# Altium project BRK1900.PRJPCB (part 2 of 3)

## Sheet Expansion-MC2.SchDoc: BRK1900 - Expansion MC2
size C; Organization: Opal Kelly; Address1: 13500 SW 72nd Ave STE 100; Address2: Portland, OR  97223; Address3: 217.391.3724; Address4: http://www.opalkelly.com; DocumentNumber: 3; Revision: 1; SheetNumber: 3; SheetTotal: 11; PageSetup: Record=PageOptions¦CenterHorizontal=True¦CenterVertical=True¦PrintScale=0.52¦XCorrection=1.00¦YCorrection=1.00¦PrintKind=0¦BorderSize=5000000¦LeftOffset=0¦BottomOffset=0¦Orientation=2¦PaperLength=1000¦PaperWidth=1000¦Scale=100¦PaperSource=7¦PrintQuality=-4¦MediaType=1¦DitherType=10¦PaperKind=Letter¦PrintScaleMode=1
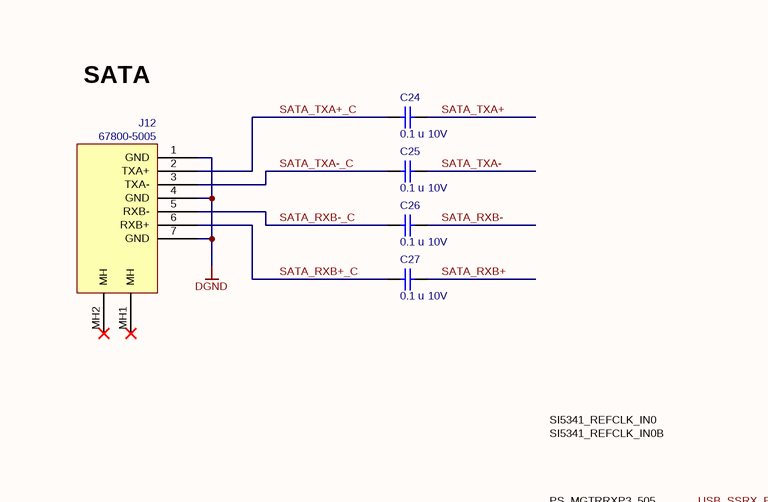
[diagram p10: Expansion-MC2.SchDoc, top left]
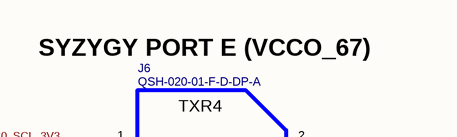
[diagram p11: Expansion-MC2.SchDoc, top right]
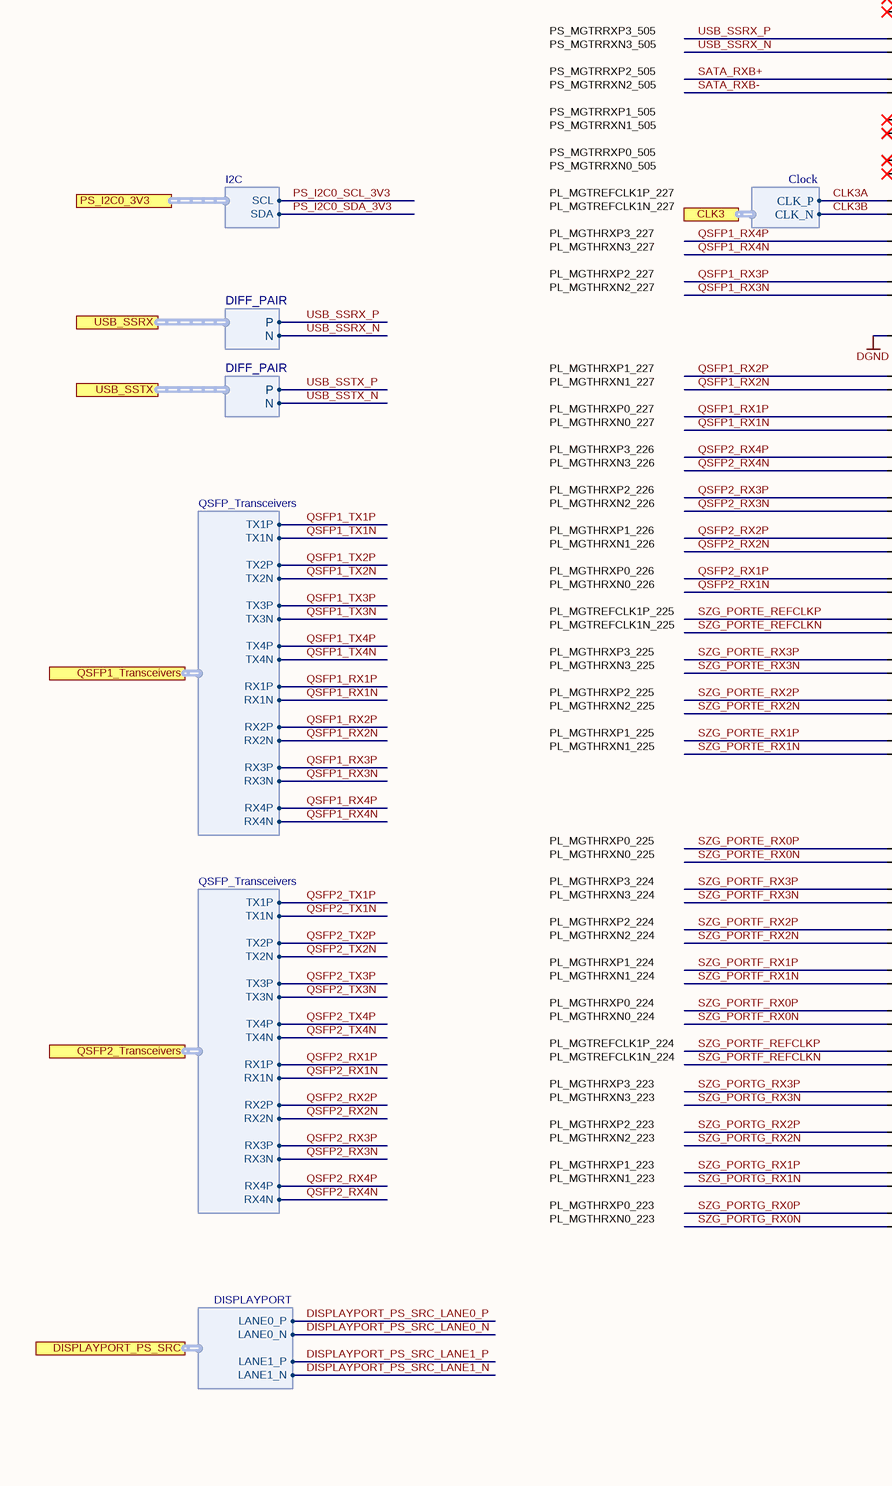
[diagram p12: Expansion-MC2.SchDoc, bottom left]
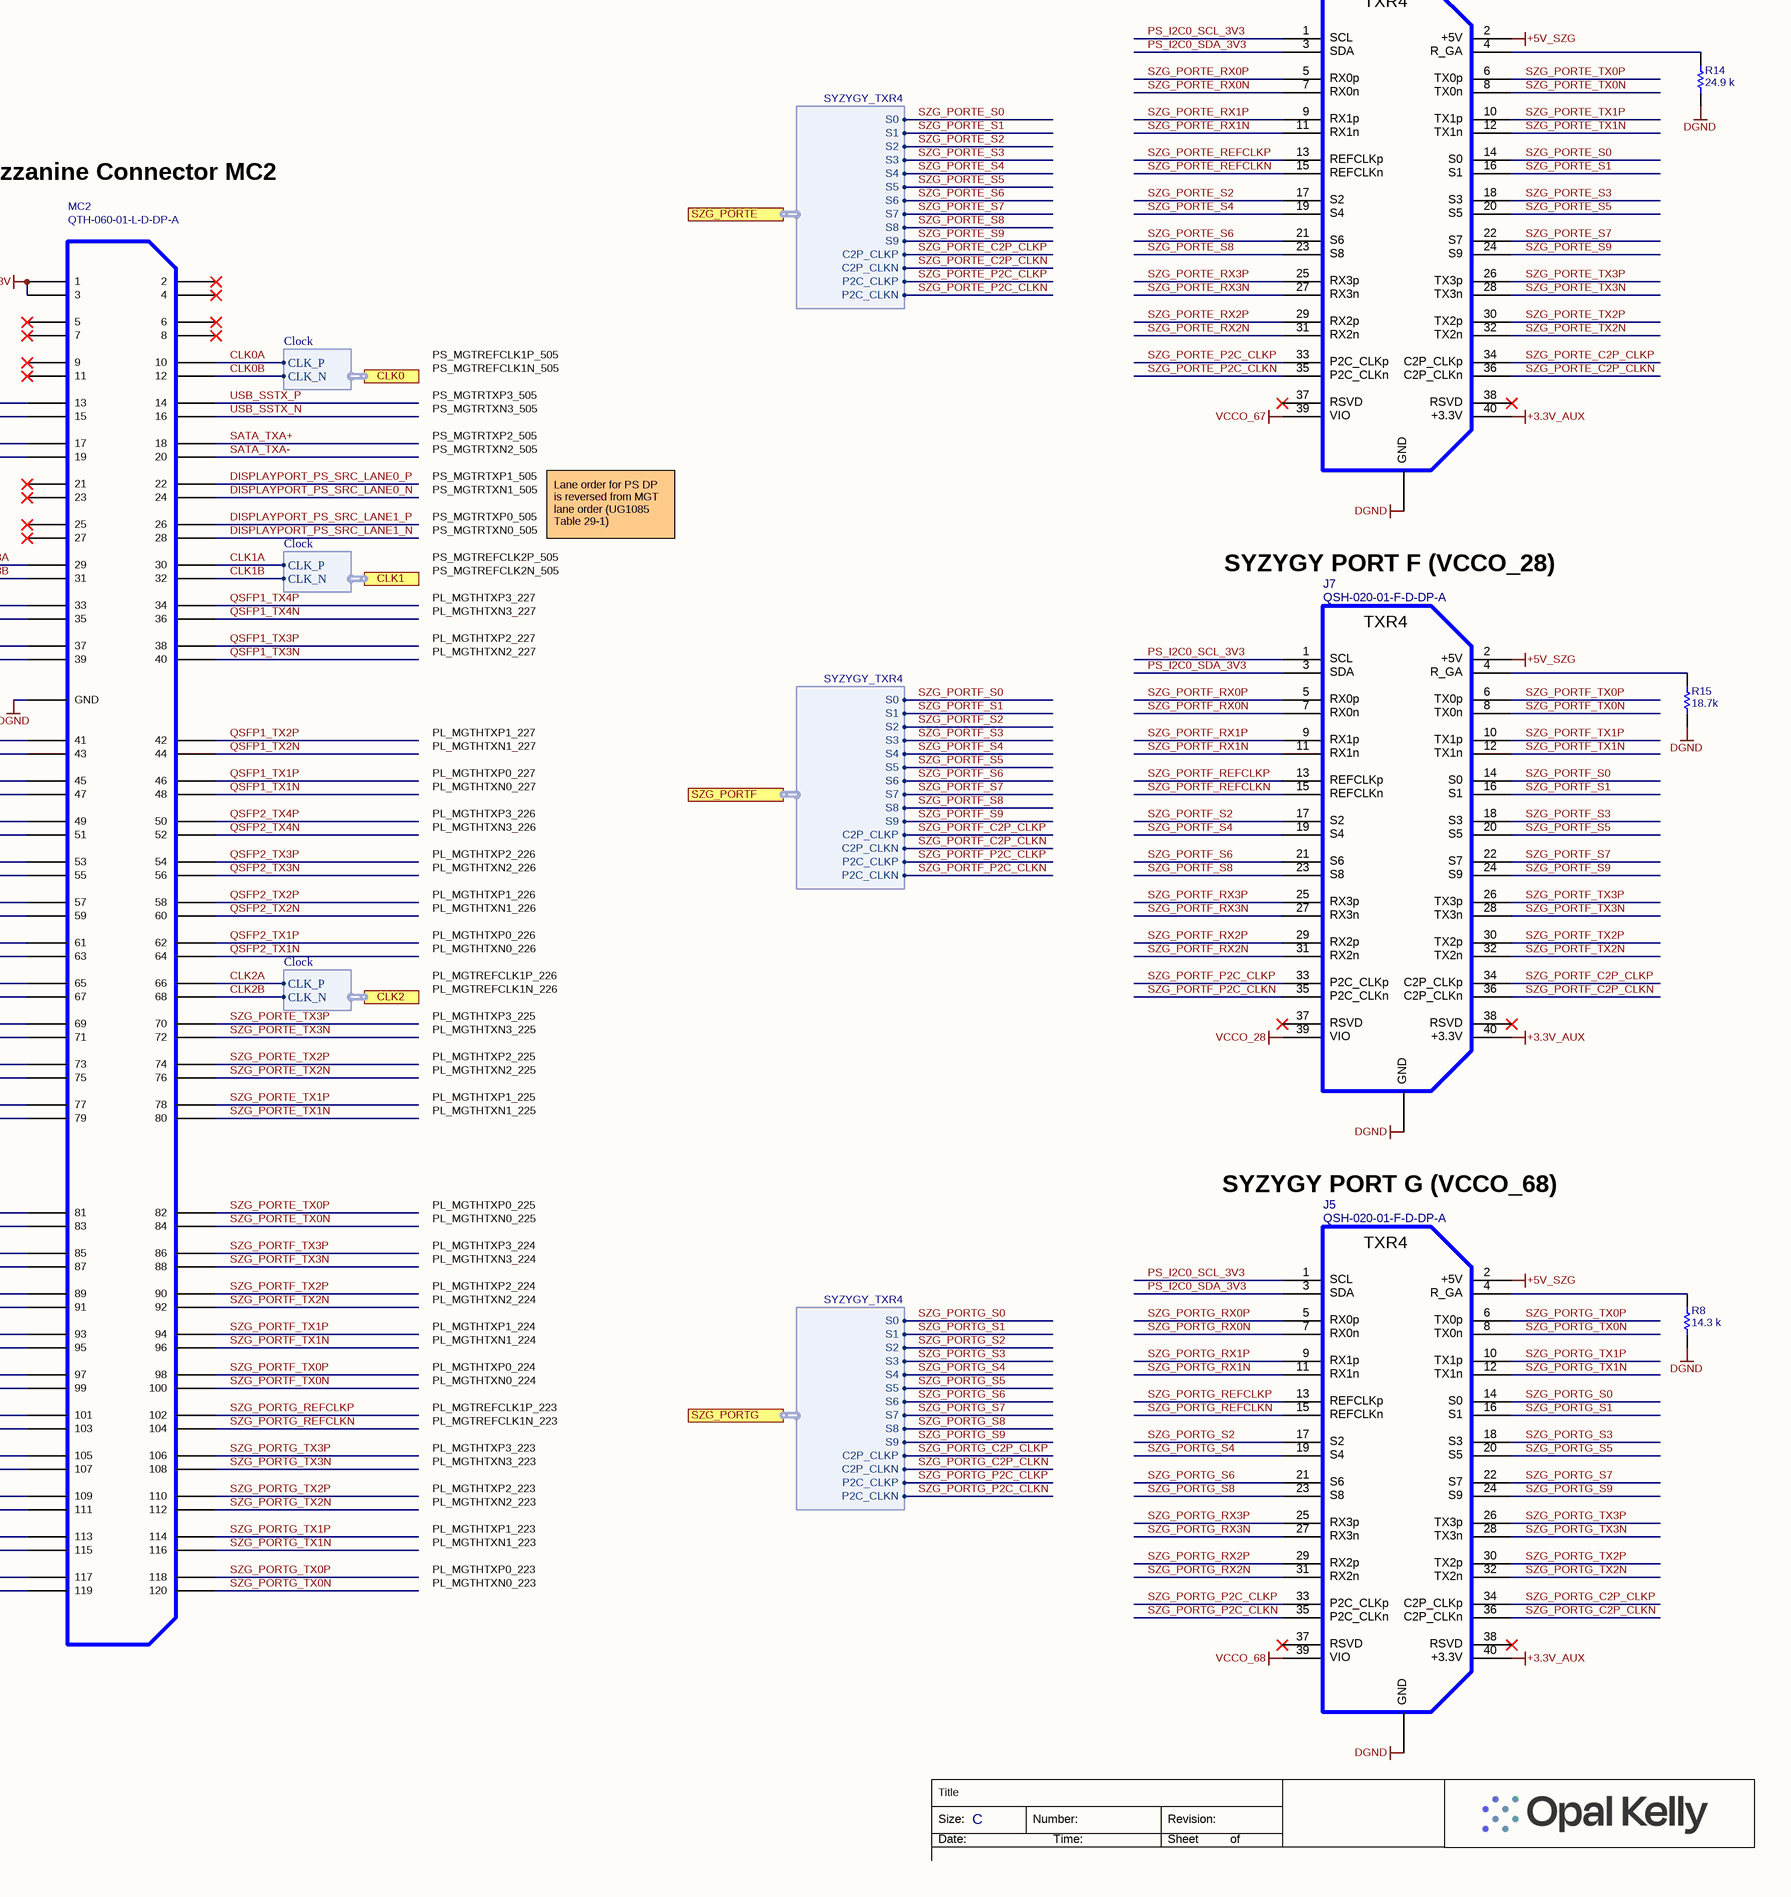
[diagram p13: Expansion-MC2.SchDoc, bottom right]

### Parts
C24  value 0.1 u  Voltage: 10V  [CAPC1005X06A]  (hidden comment: SM-0402, 10%, 10v)
C25  value 0.1 u  Voltage: 10V  [CAPC1005X06A]  (hidden comment: SM-0402, 10%, 10v)
C26  value 0.1 u  Voltage: 10V  [CAPC1005X06A]  (hidden comment: SM-0402, 10%, 10v)
C27  value 0.1 u  Voltage: 10V  [CAPC1005X06A]  (hidden comment: SM-0402, 10%, 10v)
J5  QSH-020-01-F-D-DP-A  [QSH-020-01-X-D-DP-A-L-SYZYGY]
J6  QSH-020-01-F-D-DP-A  [QSH-020-01-X-D-DP-A-L-SYZYGY]
J7  QSH-020-01-F-D-DP-A  [QSH-020-01-X-D-DP-A-L-SYZYGY]
J12  67800-5005  [MOLEX-67800-5005]
MC2  QTH-060-01-L-D-DP-A  [QTH-060-01-X-D-DP-A]
R8  value 14.3 k  [RESC1005X06A]  (hidden comment: RC0402FR-0714K3L)
R14  value 24.9 k  [RESC1005X06A]  (hidden comment: CRCW040224K9FKED)
R15  value 18.7k  [RESC1005X06A]  (hidden comment: CRCW040218K7FKED)

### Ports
CLK0 (harness Clock), CLK1 (harness Clock), CLK2 (harness Clock), CLK3 (harness Clock), DISPLAYPORT_PS_SRC (harness DISPLAYPORT), PS_I2C0_3V3 (harness I2C), QSFP1_Transceivers (harness QSFP_Transceivers), QSFP2_Transceivers (harness QSFP_Transceivers), SZG_PORTE (harness SYZYGY_TXR4), SZG_PORTF (harness SYZYGY_TXR4), SZG_PORTG (harness SYZYGY_TXR4), USB_SSRX (harness DIFF_PAIR), USB_SSTX (harness DIFF_PAIR)

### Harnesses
QSFP_Transceivers: TX1P, TX1N, TX2P, TX2N, TX3P, TX3N, TX4P, TX4N, RX1P, RX1N, RX2P, RX2N, RX3P, RX3N, RX4P, RX4N
DIFF_PAIR: P, N
SYZYGY_TXR4: S0, S1, S2, S3, S4, S5, S6, S7, S8, S9, C2P_CLKP, C2P_CLKN, P2C_CLKP, P2C_CLKN
I2C: SCL, SDA
Clock: CLK_P, CLK_N
DISPLAYPORT: LANE0_P, LANE0_N, LANE1_P, LANE1_N

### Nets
+1.8V: MC2.1 MC2.3
+3.3V_AUX: J5.40 J6.40 J7.40
+5V_SZG: J5.2 J6.2 J7.2
DGND: J5.0(GND) J6.0(GND) J7.0(GND) J12.1(GND) J12.4(GND) J12.7(GND) MC2.0(GND) R8.1 R14.1 R15.1
VCCO_28: J7.39
VCCO_67: J6.39
VCCO_68: J5.39
CLK0A: MC2.10 ; port CLK0.CLK_P
CLK0B: MC2.12 ; port CLK0.CLK_N
CLK1A: MC2.30 ; port CLK1.CLK_P
CLK1B: MC2.32 ; port CLK1.CLK_N
CLK2A: MC2.66 ; port CLK2.CLK_P
CLK2B: MC2.68 ; port CLK2.CLK_N
CLK3A: MC2.29 ; port CLK3.CLK_P
CLK3B: MC2.31 ; port CLK3.CLK_N
DISPLAYPORT_PS_SRC_LANE0_N: MC2.24 ; port DISPLAYPORT_PS_SRC.LANE0_N
DISPLAYPORT_PS_SRC_LANE0_P: MC2.22 ; port DISPLAYPORT_PS_SRC.LANE0_P
DISPLAYPORT_PS_SRC_LANE1_N: MC2.28 ; port DISPLAYPORT_PS_SRC.LANE1_N
DISPLAYPORT_PS_SRC_LANE1_P: MC2.26 ; port DISPLAYPORT_PS_SRC.LANE1_P
PS_I2C0_SCL_3V3: J5.1 J6.1 J7.1 ; port PS_I2C0_3V3.SCL
PS_I2C0_SDA_3V3: J5.3 J6.3 J7.3 ; port PS_I2C0_3V3.SDA
QSFP1_RX1N: MC2.47 ; port QSFP1_Transceivers.RX1N
QSFP1_RX1P: MC2.45 ; port QSFP1_Transceivers.RX1P
QSFP1_RX2N: MC2.43 ; port QSFP1_Transceivers.RX2N
QSFP1_RX2P: MC2.41 ; port QSFP1_Transceivers.RX2P
QSFP1_RX3N: MC2.39 ; port QSFP1_Transceivers.RX3N
QSFP1_RX3P: MC2.37 ; port QSFP1_Transceivers.RX3P
QSFP1_RX4N: MC2.35 ; port QSFP1_Transceivers.RX4N
QSFP1_RX4P: MC2.33 ; port QSFP1_Transceivers.RX4P
QSFP1_TX1N: MC2.48 ; port QSFP1_Transceivers.TX1N
QSFP1_TX1P: MC2.46 ; port QSFP1_Transceivers.TX1P
QSFP1_TX2N: MC2.44 ; port QSFP1_Transceivers.TX2N
QSFP1_TX2P: MC2.42 ; port QSFP1_Transceivers.TX2P
QSFP1_TX3N: MC2.40 ; port QSFP1_Transceivers.TX3N
QSFP1_TX3P: MC2.38 ; port QSFP1_Transceivers.TX3P
QSFP1_TX4N: MC2.36 ; port QSFP1_Transceivers.TX4N
QSFP1_TX4P: MC2.34 ; port QSFP1_Transceivers.TX4P
QSFP2_RX1N: MC2.63 ; port QSFP2_Transceivers.RX1N
QSFP2_RX1P: MC2.61 ; port QSFP2_Transceivers.RX1P
QSFP2_RX2N: MC2.59 ; port QSFP2_Transceivers.RX2N
QSFP2_RX2P: MC2.57 ; port QSFP2_Transceivers.RX2P
QSFP2_RX3N: MC2.55 ; port QSFP2_Transceivers.RX3N
QSFP2_RX3P: MC2.53 ; port QSFP2_Transceivers.RX3P
QSFP2_RX4N: MC2.51 ; port QSFP2_Transceivers.RX4N
QSFP2_RX4P: MC2.49 ; port QSFP2_Transceivers.RX4P
QSFP2_TX1N: MC2.64 ; port QSFP2_Transceivers.TX1N
QSFP2_TX1P: MC2.62 ; port QSFP2_Transceivers.TX1P
QSFP2_TX2N: MC2.60 ; port QSFP2_Transceivers.TX2N
QSFP2_TX2P: MC2.58 ; port QSFP2_Transceivers.TX2P
QSFP2_TX3N: MC2.56 ; port QSFP2_Transceivers.TX3N
QSFP2_TX3P: MC2.54 ; port QSFP2_Transceivers.TX3P
QSFP2_TX4N: MC2.52 ; port QSFP2_Transceivers.TX4N
QSFP2_TX4P: MC2.50 ; port QSFP2_Transceivers.TX4P
SATA_RXB+: C27.2 MC2.17
SATA_RXB+_C: C27.1 J12.6(RXB+)
SATA_RXB-: C26.2 MC2.19
SATA_RXB-_C: C26.1 J12.5(RXB-)
SATA_TXA+: C24.2 MC2.18
SATA_TXA+_C: C24.1 J12.2(TXA+)
SATA_TXA-: C25.2 MC2.20
SATA_TXA-_C: C25.1 J12.3(TXA-)
SZG_PORTE_C2P_CLKN: J6.36 ; port SZG_PORTE.C2P_CLKN
SZG_PORTE_C2P_CLKP: J6.34 ; port SZG_PORTE.C2P_CLKP
SZG_PORTE_P2C_CLKN: J6.35 ; port SZG_PORTE.P2C_CLKN
SZG_PORTE_P2C_CLKP: J6.33 ; port SZG_PORTE.P2C_CLKP
SZG_PORTE_REFCLKN: J6.15 MC2.67
SZG_PORTE_REFCLKP: J6.13 MC2.65
SZG_PORTE_RX0N: J6.7 MC2.83
SZG_PORTE_RX0P: J6.5 MC2.81
SZG_PORTE_RX1N: J6.11 MC2.79
SZG_PORTE_RX1P: J6.9 MC2.77
SZG_PORTE_RX2N: J6.31 MC2.75
SZG_PORTE_RX2P: J6.29 MC2.73
SZG_PORTE_RX3N: J6.27 MC2.71
SZG_PORTE_RX3P: J6.25 MC2.69
SZG_PORTE_S0: J6.14 ; port SZG_PORTE.S0
SZG_PORTE_S1: J6.16 ; port SZG_PORTE.S1
SZG_PORTE_S2: J6.17 ; port SZG_PORTE.S2
SZG_PORTE_S3: J6.18 ; port SZG_PORTE.S3
SZG_PORTE_S4: J6.19 ; port SZG_PORTE.S4
SZG_PORTE_S5: J6.20 ; port SZG_PORTE.S5
SZG_PORTE_S6: J6.21 ; port SZG_PORTE.S6
SZG_PORTE_S7: J6.22 ; port SZG_PORTE.S7
SZG_PORTE_S8: J6.23 ; port SZG_PORTE.S8
SZG_PORTE_S9: J6.24 ; port SZG_PORTE.S9
SZG_PORTE_TX0N: J6.8 MC2.84
SZG_PORTE_TX0P: J6.6 MC2.82
SZG_PORTE_TX1N: J6.12 MC2.80
SZG_PORTE_TX1P: J6.10 MC2.78
SZG_PORTE_TX2N: J6.32 MC2.76
SZG_PORTE_TX2P: J6.30 MC2.74
SZG_PORTE_TX3N: J6.28 MC2.72
SZG_PORTE_TX3P: J6.26 MC2.70
SZG_PORTF_C2P_CLKN: J7.36 ; port SZG_PORTF.C2P_CLKN
SZG_PORTF_C2P_CLKP: J7.34 ; port SZG_PORTF.C2P_CLKP
SZG_PORTF_P2C_CLKN: J7.35 ; port SZG_PORTF.P2C_CLKN
SZG_PORTF_P2C_CLKP: J7.33 ; port SZG_PORTF.P2C_CLKP
SZG_PORTF_REFCLKN: J7.15 MC2.103
SZG_PORTF_REFCLKP: J7.13 MC2.101
SZG_PORTF_RX0N: J7.7 MC2.99
SZG_PORTF_RX0P: J7.5 MC2.97
SZG_PORTF_RX1N: J7.11 MC2.95
SZG_PORTF_RX1P: J7.9 MC2.93
SZG_PORTF_RX2N: J7.31 MC2.91
SZG_PORTF_RX2P: J7.29 MC2.89
SZG_PORTF_RX3N: J7.27 MC2.87
SZG_PORTF_RX3P: J7.25 MC2.85
SZG_PORTF_S0: J7.14 ; port SZG_PORTF.S0
SZG_PORTF_S1: J7.16 ; port SZG_PORTF.S1
SZG_PORTF_S2: J7.17 ; port SZG_PORTF.S2
SZG_PORTF_S3: J7.18 ; port SZG_PORTF.S3
SZG_PORTF_S4: J7.19 ; port SZG_PORTF.S4
SZG_PORTF_S5: J7.20 ; port SZG_PORTF.S5
SZG_PORTF_S6: J7.21 ; port SZG_PORTF.S6
SZG_PORTF_S7: J7.22 ; port SZG_PORTF.S7
SZG_PORTF_S8: J7.23 ; port SZG_PORTF.S8
SZG_PORTF_S9: J7.24 ; port SZG_PORTF.S9
SZG_PORTF_TX0N: J7.8 MC2.100
SZG_PORTF_TX0P: J7.6 MC2.98
SZG_PORTF_TX1N: J7.12 MC2.96
SZG_PORTF_TX1P: J7.10 MC2.94
SZG_PORTF_TX2N: J7.32 MC2.92
SZG_PORTF_TX2P: J7.30 MC2.90
SZG_PORTF_TX3N: J7.28 MC2.88
SZG_PORTF_TX3P: J7.26 MC2.86
SZG_PORTG_C2P_CLKN: J5.36 ; port SZG_PORTG.C2P_CLKN
SZG_PORTG_C2P_CLKP: J5.34 ; port SZG_PORTG.C2P_CLKP
SZG_PORTG_P2C_CLKN: J5.35 ; port SZG_PORTG.P2C_CLKN
SZG_PORTG_P2C_CLKP: J5.33 ; port SZG_PORTG.P2C_CLKP
SZG_PORTG_REFCLKN: J5.15 MC2.104
SZG_PORTG_REFCLKP: J5.13 MC2.102
SZG_PORTG_RX0N: J5.7 MC2.119
SZG_PORTG_RX0P: J5.5 MC2.117
SZG_PORTG_RX1N: J5.11 MC2.115
SZG_PORTG_RX1P: J5.9 MC2.113
SZG_PORTG_RX2N: J5.31 MC2.111
SZG_PORTG_RX2P: J5.29 MC2.109
SZG_PORTG_RX3N: J5.27 MC2.107
SZG_PORTG_RX3P: J5.25 MC2.105
SZG_PORTG_S0: J5.14 ; port SZG_PORTG.S0
SZG_PORTG_S1: J5.16 ; port SZG_PORTG.S1
SZG_PORTG_S2: J5.17 ; port SZG_PORTG.S2
SZG_PORTG_S3: J5.18 ; port SZG_PORTG.S3
SZG_PORTG_S4: J5.19 ; port SZG_PORTG.S4
SZG_PORTG_S5: J5.20 ; port SZG_PORTG.S5
SZG_PORTG_S6: J5.21 ; port SZG_PORTG.S6
SZG_PORTG_S7: J5.22 ; port SZG_PORTG.S7
SZG_PORTG_S8: J5.23 ; port SZG_PORTG.S8
SZG_PORTG_S9: J5.24 ; port SZG_PORTG.S9
SZG_PORTG_TX0N: J5.8 MC2.120
SZG_PORTG_TX0P: J5.6 MC2.118
SZG_PORTG_TX1N: J5.12 MC2.116
SZG_PORTG_TX1P: J5.10 MC2.114
SZG_PORTG_TX2N: J5.32 MC2.112
SZG_PORTG_TX2P: J5.30 MC2.110
SZG_PORTG_TX3N: J5.28 MC2.108
SZG_PORTG_TX3P: J5.26 MC2.106
USB_SSRX_N: MC2.15 ; port USB_SSRX.N
USB_SSRX_P: MC2.13 ; port USB_SSRX.P
USB_SSTX_N: MC2.16 ; port USB_SSTX.N
USB_SSTX_P: MC2.14 ; port USB_SSTX.P
NetJ5_4: J5.4 R8.2
NetJ6_4: J6.4 R14.2
NetJ7_4: J7.4 R15.2

Not connected (* = marked no-connect by the designer): J5 37* 38*; J6 37* 38*; J7 37* 38*; J12 MH1(MH)* MH2(MH)*; MC2 2* 4* 5* 6* 7* 8* 9* 11* 21* 23* 25* 27*

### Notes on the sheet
- SYZYGY PORT E (VCCO_67)
- SATA
- Mezzanine Connector MC2
- SI5341_REFCLK_IN0
- SI5341_REFCLK_IN0B
- PS_MGTREFCLK1P_505
- PS_MGTREFCLK1N_505
- PS_MGTRRXP3_505
- PS_MGTRRXN3_505
- PS_MGTRRXP2_505
- PS_MGTRTXP3_505
- PS_MGTRTXN3_505
- PS_MGTRTXP2_505
- PS_MGTRRXN2_505
- PS_MGTRRXP1_505
- PS_MGTRRXN1_505
- PS_MGTRTXN2_505
- PS_MGTRTXP1_505
- PS_MGTRTXN1_505
- PS_MGTRRXP0_505
- PS_MGTRRXN0_505
- PL_MGTREFCLK1P_227
- PL_MGTREFCLK1N_227
- PS_MGTRTXP0_505
- PS_MGTRTXN0_505
- PS_MGTREFCLK2P_505
- PS_MGTREFCLK2N_505
- Lane order for PS DP is reversed from MGT lane order (UG1085 Table 29-1)
- SYZYGY PORT F (VCCO_28)
- PL_MGTHRXP3_227
- PL_MGTHRXN3_227
- PL_MGTHRXP2_227
- PL_MGTHTXP3_227
- PL_MGTHTXN3_227
- PL_MGTHTXP2_227
- PL_MGTHRXN2_227
- PL_MGTHTXN2_227
- PL_MGTHRXN1_227
- PL_MGTHRXP1_227
- PL_MGTHRXP0_227
- PL_MGTHTXP1_227
- PL_MGTHTXN1_227
- PL_MGTHTXP0_227
- PL_MGTHRXN0_227
- PL_MGTHRXP3_226
- PL_MGTHRXN3_226
- PL_MGTHTXN0_227
- PL_MGTHTXP3_226
- PL_MGTHTXN3_226
- PL_MGTHRXP2_226
- PL_MGTHRXN2_226
- PL_MGTHRXP1_226
- PL_MGTHRXN1_226
- PL_MGTHTXP2_226
- PL_MGTHTXN2_226
- PL_MGTHTXP1_226
- PL_MGTHTXN1_226
- PL_MGTHRXP0_226
- PL_MGTHRXN0_226
- PL_MGTREFCLK1P_225
- PL_MGTHTXP0_226
- PL_MGTHTXN0_226
- PL_MGTREFCLK1P_226
- PL_MGTREFCLK1N_225
- PL_MGTHRXP3_225
- PL_MGTHRXN3_225
- PL_MGTREFCLK1N_226
- PL_MGTHTXP3_225
- PL_MGTHTXN3_225
- PL_MGTHRXP2_225
- PL_MGTHRXN2_225
- PL_MGTHRXP1_225
- PL_MGTHRXN1_225
- PL_MGTHTXP2_225
- PL_MGTHTXN2_225
- PL_MGTHTXP1_225
- PL_MGTHTXN1_225
- PL_MGTHRXP0_225
- PL_MGTHRXN0_225
- PL_MGTHRXP3_224
- PL_MGTHTXP0_225
- PL_MGTHTXN0_225
- PL_MGTHTXP3_224
- SYZYGY PORT G (VCCO_68)
- PL_MGTHRXN3_224
- PL_MGTHRXP2_224
- PL_MGTHRXN2_224
- PL_MGTHTXN3_224
- PL_MGTHTXP2_224
- PL_MGTHTXN2_224
- PL_MGTHRXP1_224
- PL_MGTHRXN1_224
- PL_MGTHRXP0_224
- PL_MGTHRXN0_224
- PL_MGTHTXP1_224
- PL_MGTHTXN1_224
- PL_MGTHTXP0_224
- PL_MGTHTXN0_224
- PL_MGTREFCLK1P_224
- PL_MGTREFCLK1N_224
- PL_MGTHRXP3_223
- PL_MGTREFCLK1P_223
- PL_MGTREFCLK1N_223
- PL_MGTHTXP3_223
- PL_MGTHRXN3_223
- PL_MGTHRXP2_223
- PL_MGTHRXN2_223
- PL_MGTHTXN3_223
- PL_MGTHTXP2_223
- PL_MGTHTXN2_223
- PL_MGTHRXP1_223
- PL_MGTHRXN1_223
- PL_MGTHRXP0_223
- PL_MGTHRXN0_223
- PL_MGTHTXP1_223
- PL_MGTHTXN1_223
- PL_MGTHTXP0_223
- PL_MGTHTXN0_223
- Title
- Size:
- Date:
- C
- Number:
- Time:
- Revision:
- Sheet
- of

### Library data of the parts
C24-C27 = 000070: Partnumber: 000070; manufacturer: Kemet; manufacturer_pn: C0402C104K8PACTU; ValueFloat: 1E-7; id: 750; inventory_price: 0.0023; reorder_quantity: 70000; x_tolerance: 10
J5-J7 = 000694: 0.5mm hi-speed, high-density socket (male); Partnumber: 000694; manufacturer: Samtec; Description 2: 20 Differential Pairs (40-pin), ground protection in middle
J12 = 000988: SATA 7-pin receptacle; Manufacturer: Molex; partnumber: 000988; Description 2: Vertical Mount, SMD, Latch, 15u Gold
MC2 = 001769: Partnumber: 001769; manufacturer: Samtec
R8 = 002203: Thick-film resistor; Partnumber: 002203; Manufacturer: Yageo; ValueFloat: 14300; Tolerance (%): 1; Description 2: SM-0402, 1%, 1/16W
R14 = 000934: Partnumber: 000934; manufacturer: Vishay; ValueFloat: 24900; x_tolerance: 1
R15 = 001783: Partnumber: 001783; manufacturer: Vishay; ValueFloat: 18700; x_tolerance: 1

## Sheet Expansion-MC3.SchDoc: BRK1900 - Expansion MC3
size C; Organization: Opal Kelly; Address1: 13500 SW 72nd Ave STE 100; Address2: Portland, OR  97223; Address3: Portland, OR  97223; Address4: http://www.opalkelly.com; DocumentNumber: 4; Revision: 1; SheetNumber: 4; SheetTotal: 11; PageSetup: Record=PageOptions¦CenterHorizontal=True¦CenterVertical=True¦PrintScale=0.52¦XCorrection=1.00¦YCorrection=1.00¦PrintKind=0¦BorderSize=5000000¦LeftOffset=0¦BottomOffset=0¦Orientation=2¦PaperLength=1000¦PaperWidth=1000¦Scale=100¦PaperSource=7¦PrintQuality=-4¦MediaType=1¦DitherType=10¦PaperKind=Letter¦PrintScaleMode=1
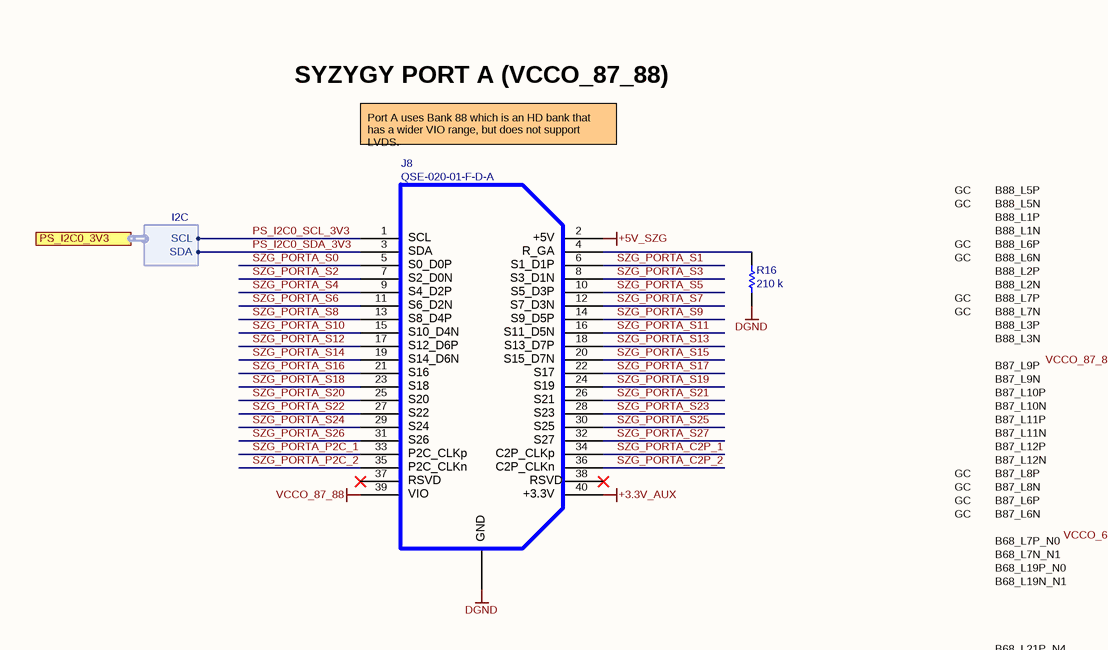
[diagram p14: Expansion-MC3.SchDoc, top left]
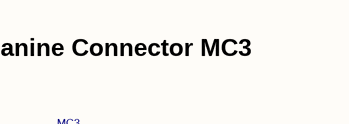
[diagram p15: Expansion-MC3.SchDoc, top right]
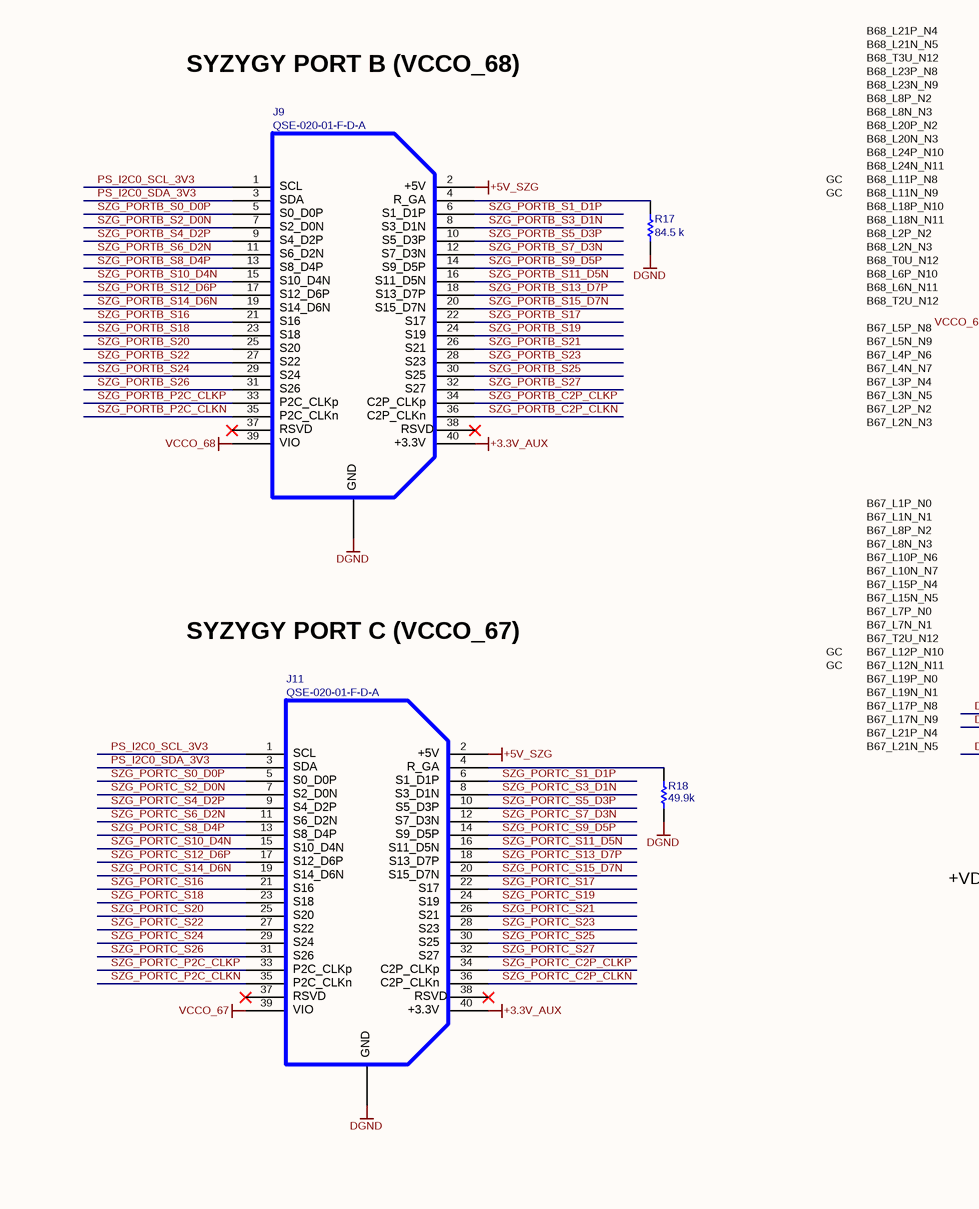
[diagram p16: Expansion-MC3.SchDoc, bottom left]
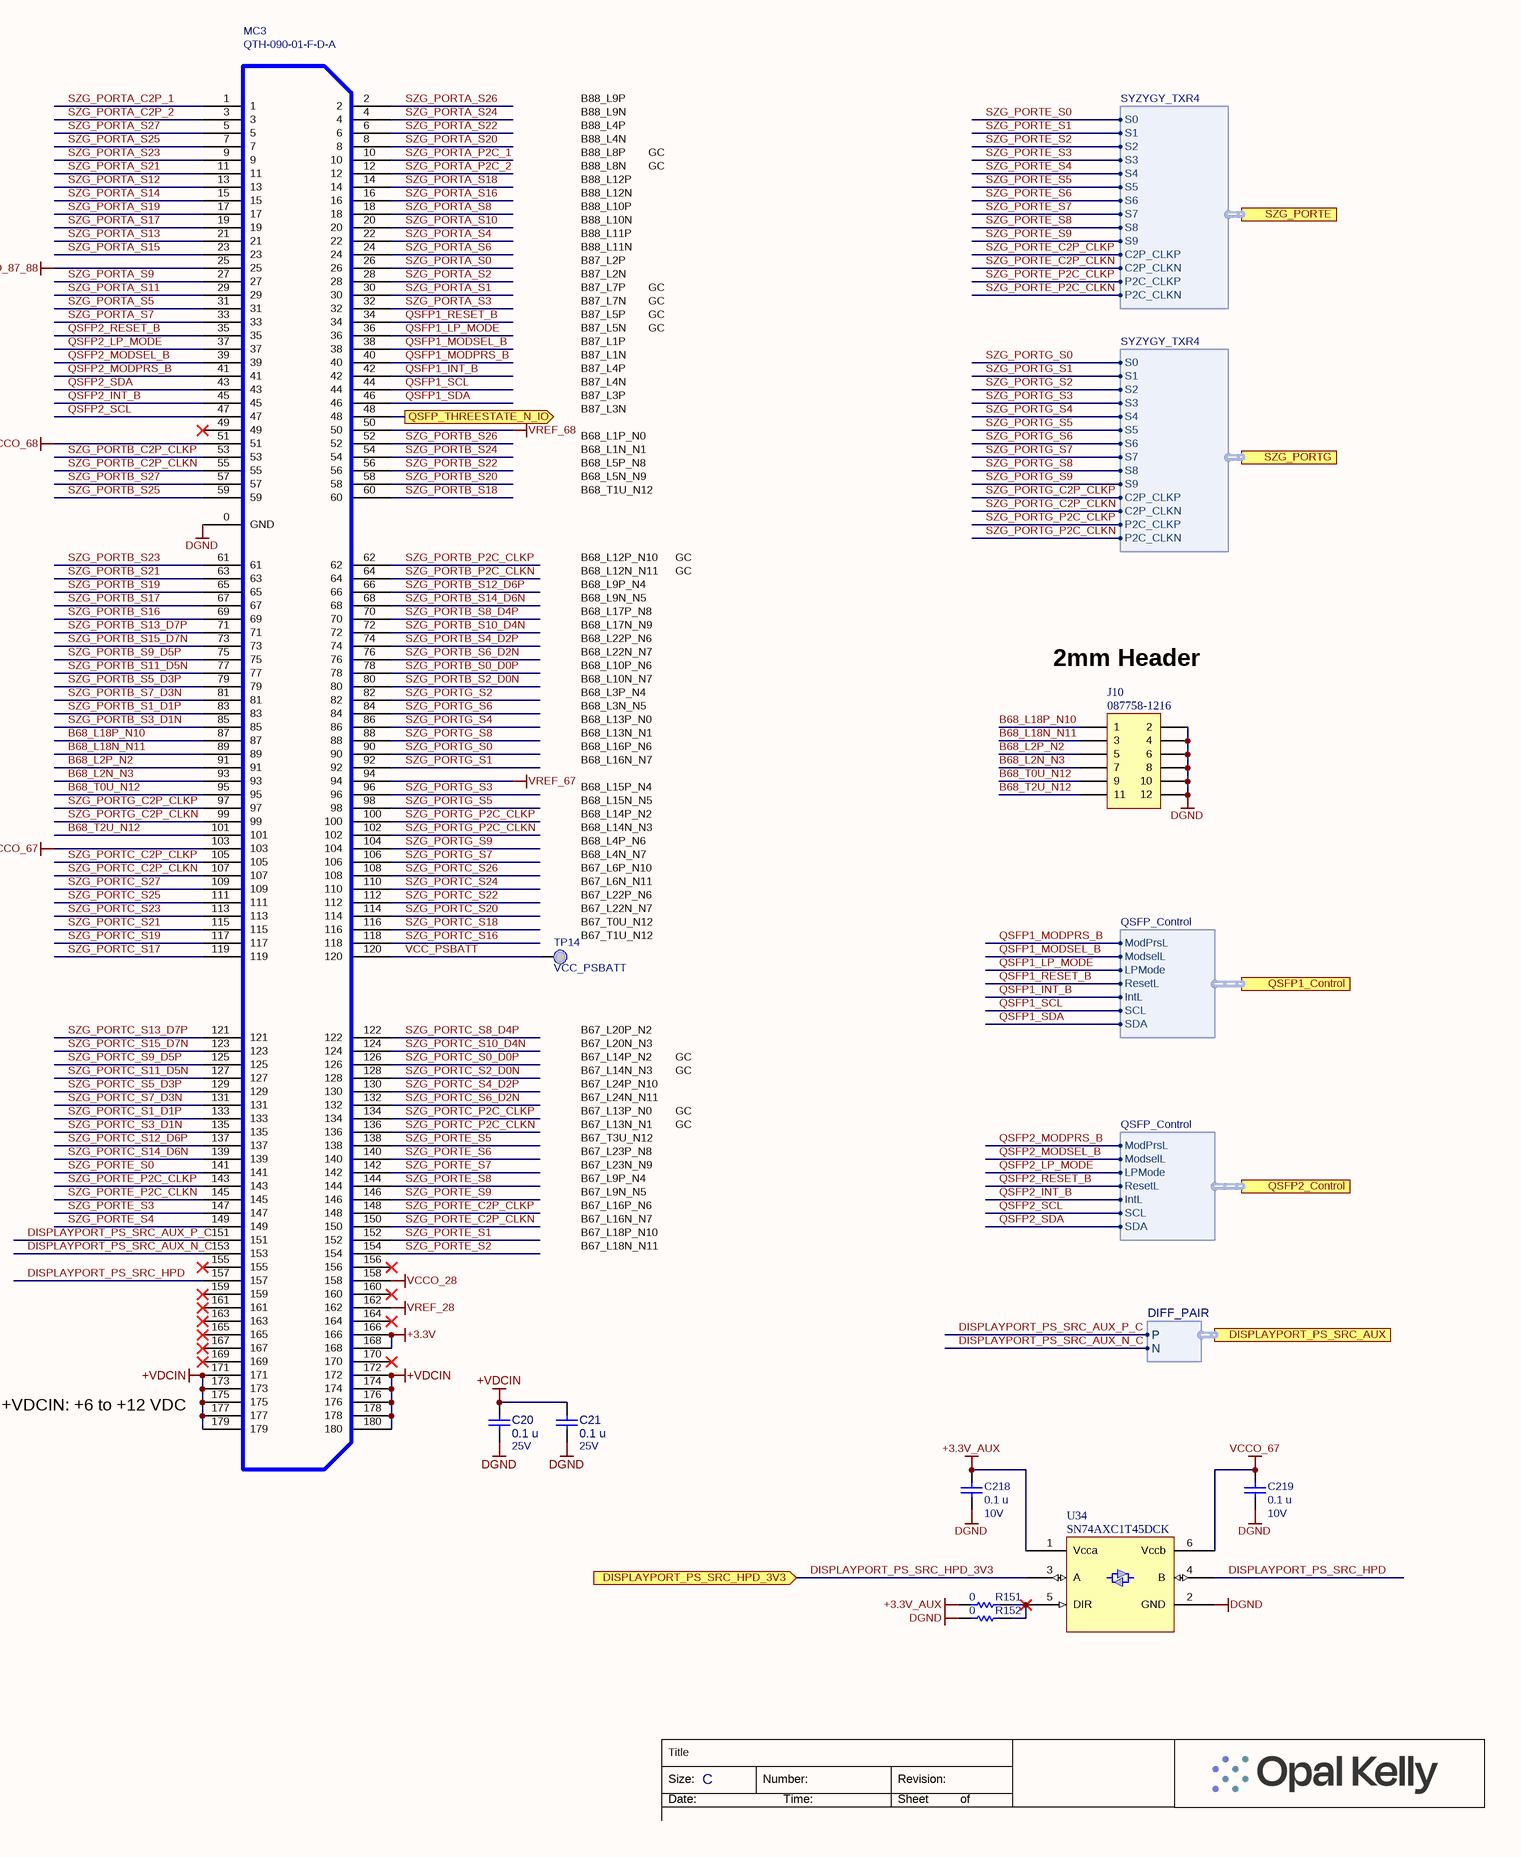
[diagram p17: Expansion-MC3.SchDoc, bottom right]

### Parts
C20  value 0.1 u  Voltage: 25V  [CAPC1005X06A]  (hidden comment: TMK105BJ104KV-F)
C21  value 0.1 u  Voltage: 25V  [CAPC1005X06A]  (hidden comment: TMK105BJ104KV-F)
C218  value 0.1 u  Voltage: 10V  [CAPC1005X06A]  (hidden comment: C0402C104K8PACTU)
C219  value 0.1 u  Voltage: 10V  [CAPC1005X06A]  (hidden comment: C0402C104K8PACTU)
J8  QSE-020-01-F-D-A  [QSE-020-01-X-D-A-L-SYZYGY]
J9  QSE-020-01-F-D-A  [QSE-020-01-X-D-A-L-SYZYGY]
J10  087758-1216  [HDR2X6-2MM]
J11  QSE-020-01-F-D-A  [QSE-020-01-X-D-A-L-SYZYGY]
MC3  QTH-090-01-F-D-A  [QTH-090-01-X-D]
R16  value 210 k  [RESC1005X06A]  (hidden comment: CRCW0402210KFKED)
R17  value 84.5 k  [RESC1005X06A]  (hidden comment: CRCW040284K5FKED)
R18  value 49.9k  [RESC1005X06A]  (hidden comment: CRCW040249K9FKED)
R151  value 0  [RESC1005X06A]  (hidden comment: CRCW04020000Z0ED)
R152  value 0  [RESC1005X06A]  (hidden comment: CRCW04020000Z0ED)
TP14  VCC_PSBATT  [TP-PTH-25/45]
U34  SN74AXC1T45DCK  [DCK-R-PDSO-G6]

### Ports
DISPLAYPORT_PS_SRC_AUX (harness DIFF_PAIR), DISPLAYPORT_PS_SRC_HPD_3V3 (in), PS_I2C0_3V3 (harness I2C), QSFP1_Control (harness QSFP_Control), QSFP2_Control (harness QSFP_Control), QSFP_THREESTATE_N_IO (out), SZG_PORTE (harness SYZYGY_TXR4), SZG_PORTG (harness SYZYGY_TXR4)

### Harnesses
SYZYGY_TXR4: S0, S1, S2, S3, S4, S5, S6, S7, S8, S9, C2P_CLKP, C2P_CLKN, P2C_CLKP, P2C_CLKN
I2C: SCL, SDA
QSFP_Control: ModPrsL, IntL, LPMode, ModselL, ResetL, SCL, SDA
DIFF_PAIR: P, N

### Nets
+3.3V: MC3.166 MC3.168
+3.3V_AUX: C218.2 J8.40 J9.40 J11.40 R151.1 U34.1(Vcca)
+5V_SZG: J8.2 J9.2 J11.2
+VDCIN: C20.1 C21.1 MC3.171 MC3.172 MC3.173 MC3.174 MC3.175 MC3.176 MC3.177 MC3.178 MC3.179 MC3.180
DGND: C20.2 C21.2 C218.1 C219.1 J8.0 J9.0 J10.2 J10.4 J10.6 J10.8 J10.10 J10.12 J11.0 MC3.0(GND) R16.1 R17.1 R18.1 R152.1 U34.2(GND)
VCCO_28: MC3.158
VCCO_67: C219.2 J11.39 MC3.103 U34.6(Vccb)
VCCO_68: J9.39 MC3.51
VCCO_87_88: J8.39 MC3.25
VREF_28: MC3.162
VREF_67: MC3.94
VREF_68: MC3.50
B68_L2N_N3: J10.7 MC3.93
B68_L2P_N2: J10.5 MC3.91
B68_L18N_N11: J10.3 MC3.89
B68_L18P_N10: J10.1 MC3.87
B68_T0U_N12: J10.9 MC3.95
B68_T2U_N12: J10.11 MC3.101
DISPLAYPORT_PS_SRC_AUX_N_C: MC3.153 ; port DISPLAYPORT_PS_SRC_AUX.N
DISPLAYPORT_PS_SRC_AUX_P_C: MC3.151 ; port DISPLAYPORT_PS_SRC_AUX.P
DISPLAYPORT_PS_SRC_HPD: MC3.157 U34.4(B)
DISPLAYPORT_PS_SRC_HPD_3V3: U34.3(A) ; port DISPLAYPORT_PS_SRC_HPD_3V3
PS_I2C0_SCL_3V3: J8.1 J9.1 J11.1 ; port PS_I2C0_3V3.SCL
PS_I2C0_SDA_3V3: J8.3 J9.3 J11.3 ; port PS_I2C0_3V3.SDA
QSFP1_INT_B: MC3.42 ; port QSFP1_Control.IntL
QSFP1_LP_MODE: MC3.36 ; port QSFP1_Control.LPMode
QSFP1_MODPRS_B: MC3.40 ; port QSFP1_Control.ModPrsL
QSFP1_MODSEL_B: MC3.38 ; port QSFP1_Control.ModselL
QSFP1_RESET_B: MC3.34 ; port QSFP1_Control.ResetL
QSFP1_SCL: MC3.44 ; port QSFP1_Control.SCL
QSFP1_SDA: MC3.46 ; port QSFP1_Control.SDA
QSFP2_INT_B: MC3.45 ; port QSFP2_Control.IntL
QSFP2_LP_MODE: MC3.37 ; port QSFP2_Control.LPMode
QSFP2_MODPRS_B: MC3.41 ; port QSFP2_Control.ModPrsL
QSFP2_MODSEL_B: MC3.39 ; port QSFP2_Control.ModselL
QSFP2_RESET_B: MC3.35 ; port QSFP2_Control.ResetL
QSFP2_SCL: MC3.47 ; port QSFP2_Control.SCL
QSFP2_SDA: MC3.43 ; port QSFP2_Control.SDA
SZG_PORTA_C2P_1: J8.34 MC3.1
SZG_PORTA_C2P_2: J8.36 MC3.3
SZG_PORTA_P2C_1: J8.33 MC3.10
SZG_PORTA_P2C_2: J8.35 MC3.12
SZG_PORTA_S0: J8.5 MC3.26
SZG_PORTA_S1: J8.6 MC3.30
SZG_PORTA_S2: J8.7 MC3.28
SZG_PORTA_S3: J8.8 MC3.32
SZG_PORTA_S4: J8.9 MC3.22
SZG_PORTA_S5: J8.10 MC3.31
SZG_PORTA_S6: J8.11 MC3.24
SZG_PORTA_S7: J8.12 MC3.33
SZG_PORTA_S8: J8.13 MC3.18
SZG_PORTA_S9: J8.14 MC3.27
SZG_PORTA_S10: J8.15 MC3.20
SZG_PORTA_S11: J8.16 MC3.29
SZG_PORTA_S12: J8.17 MC3.13
SZG_PORTA_S13: J8.18 MC3.21
SZG_PORTA_S14: J8.19 MC3.15
SZG_PORTA_S15: J8.20 MC3.23
SZG_PORTA_S16: J8.21 MC3.16
SZG_PORTA_S17: J8.22 MC3.19
SZG_PORTA_S18: J8.23 MC3.14
SZG_PORTA_S19: J8.24 MC3.17
SZG_PORTA_S20: J8.25 MC3.8
SZG_PORTA_S21: J8.26 MC3.11
SZG_PORTA_S22: J8.27 MC3.6
SZG_PORTA_S23: J8.28 MC3.9
SZG_PORTA_S24: J8.29 MC3.4
SZG_PORTA_S25: J8.30 MC3.7
SZG_PORTA_S26: J8.31 MC3.2
SZG_PORTA_S27: J8.32 MC3.5
SZG_PORTB_C2P_CLKN: J9.36 MC3.55
SZG_PORTB_C2P_CLKP: J9.34 MC3.53
SZG_PORTB_P2C_CLKN: J9.35 MC3.64
SZG_PORTB_P2C_CLKP: J9.33 MC3.62
SZG_PORTB_S0_D0P: J9.5 MC3.78
SZG_PORTB_S1_D1P: J9.6 MC3.83
SZG_PORTB_S2_D0N: J9.7 MC3.80
SZG_PORTB_S3_D1N: J9.8 MC3.85
SZG_PORTB_S4_D2P: J9.9 MC3.74
SZG_PORTB_S5_D3P: J9.10 MC3.79
SZG_PORTB_S6_D2N: J9.11 MC3.76
SZG_PORTB_S7_D3N: J9.12 MC3.81
SZG_PORTB_S8_D4P: J9.13 MC3.70
SZG_PORTB_S9_D5P: J9.14 MC3.75
SZG_PORTB_S10_D4N: J9.15 MC3.72
SZG_PORTB_S11_D5N: J9.16 MC3.77
SZG_PORTB_S12_D6P: J9.17 MC3.66
SZG_PORTB_S13_D7P: J9.18 MC3.71
SZG_PORTB_S14_D6N: J9.19 MC3.68
SZG_PORTB_S15_D7N: J9.20 MC3.73
SZG_PORTB_S16: J9.21 MC3.69
SZG_PORTB_S17: J9.22 MC3.67
SZG_PORTB_S18: J9.23 MC3.60
SZG_PORTB_S19: J9.24 MC3.65
SZG_PORTB_S20: J9.25 MC3.58
SZG_PORTB_S21: J9.26 MC3.63
SZG_PORTB_S22: J9.27 MC3.56
SZG_PORTB_S23: J9.28 MC3.61
SZG_PORTB_S24: J9.29 MC3.54
SZG_PORTB_S25: J9.30 MC3.59
SZG_PORTB_S26: J9.31 MC3.52
SZG_PORTB_S27: J9.32 MC3.57
SZG_PORTC_C2P_CLKN: J11.36 MC3.107
SZG_PORTC_C2P_CLKP: J11.34 MC3.105
SZG_PORTC_P2C_CLKN: J11.35 MC3.136
SZG_PORTC_P2C_CLKP: J11.33 MC3.134
SZG_PORTC_S0_D0P: J11.5 MC3.126
SZG_PORTC_S1_D1P: J11.6 MC3.133
SZG_PORTC_S2_D0N: J11.7 MC3.128
SZG_PORTC_S3_D1N: J11.8 MC3.135
SZG_PORTC_S4_D2P: J11.9 MC3.130
SZG_PORTC_S5_D3P: J11.10 MC3.129
SZG_PORTC_S6_D2N: J11.11 MC3.132
SZG_PORTC_S7_D3N: J11.12 MC3.131
SZG_PORTC_S8_D4P: J11.13 MC3.122
SZG_PORTC_S9_D5P: J11.14 MC3.125
SZG_PORTC_S10_D4N: J11.15 MC3.124
SZG_PORTC_S11_D5N: J11.16 MC3.127
SZG_PORTC_S12_D6P: J11.17 MC3.137
SZG_PORTC_S13_D7P: J11.18 MC3.121
SZG_PORTC_S14_D6N: J11.19 MC3.139
SZG_PORTC_S15_D7N: J11.20 MC3.123
SZG_PORTC_S16: J11.21 MC3.118
SZG_PORTC_S17: J11.22 MC3.119
SZG_PORTC_S18: J11.23 MC3.116
SZG_PORTC_S19: J11.24 MC3.117
SZG_PORTC_S20: J11.25 MC3.114
SZG_PORTC_S21: J11.26 MC3.115
SZG_PORTC_S22: J11.27 MC3.112
SZG_PORTC_S23: J11.28 MC3.113
SZG_PORTC_S24: J11.29 MC3.110
SZG_PORTC_S25: J11.30 MC3.111
SZG_PORTC_S26: J11.31 MC3.108
SZG_PORTC_S27: J11.32 MC3.109
SZG_PORTE_C2P_CLKN: MC3.150 ; port SZG_PORTE.C2P_CLKN
SZG_PORTE_C2P_CLKP: MC3.148 ; port SZG_PORTE.C2P_CLKP
SZG_PORTE_P2C_CLKN: MC3.145 ; port SZG_PORTE.P2C_CLKN
SZG_PORTE_P2C_CLKP: MC3.143 ; port SZG_PORTE.P2C_CLKP
SZG_PORTE_S0: MC3.141 ; port SZG_PORTE.S0
SZG_PORTE_S1: MC3.152 ; port SZG_PORTE.S1
SZG_PORTE_S2: MC3.154 ; port SZG_PORTE.S2
SZG_PORTE_S3: MC3.147 ; port SZG_PORTE.S3
SZG_PORTE_S4: MC3.149 ; port SZG_PORTE.S4
SZG_PORTE_S5: MC3.138 ; port SZG_PORTE.S5
SZG_PORTE_S6: MC3.140 ; port SZG_PORTE.S6
SZG_PORTE_S7: MC3.142 ; port SZG_PORTE.S7
SZG_PORTE_S8: MC3.144 ; port SZG_PORTE.S8
SZG_PORTE_S9: MC3.146 ; port SZG_PORTE.S9
SZG_PORTG_C2P_CLKN: MC3.99 ; port SZG_PORTG.C2P_CLKN
SZG_PORTG_C2P_CLKP: MC3.97 ; port SZG_PORTG.C2P_CLKP
SZG_PORTG_P2C_CLKN: MC3.102 ; port SZG_PORTG.P2C_CLKN
SZG_PORTG_P2C_CLKP: MC3.100 ; port SZG_PORTG.P2C_CLKP
SZG_PORTG_S0: MC3.90 ; port SZG_PORTG.S0
SZG_PORTG_S1: MC3.92 ; port SZG_PORTG.S1
SZG_PORTG_S2: MC3.82 ; port SZG_PORTG.S2
SZG_PORTG_S3: MC3.96 ; port SZG_PORTG.S3
SZG_PORTG_S4: MC3.86 ; port SZG_PORTG.S4
SZG_PORTG_S5: MC3.98 ; port SZG_PORTG.S5
SZG_PORTG_S6: MC3.84 ; port SZG_PORTG.S6
SZG_PORTG_S7: MC3.106 ; port SZG_PORTG.S7
SZG_PORTG_S8: MC3.88 ; port SZG_PORTG.S8
SZG_PORTG_S9: MC3.104 ; port SZG_PORTG.S9
VCC_PSBATT: MC3.120 TP14.1(PIN)
NetJ8_4: J8.4 R16.2
NetJ9_4: J9.4 R17.2
NetJ11_4: J11.4 R18.2
NetMC3_48: MC3.48 ; port QSFP_THREESTATE_N_IO
NetR151_2: R151.2 R152.2 U34.5(DIR)

Not connected (* = marked no-connect by the designer): J8 37* 38*; J9 37* 38*; J11 37* 38*; MC3 49* 155* 156* 159* 160* 161* 163* 164* 165* 167* 169* 170*

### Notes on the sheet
- SYZYGY PORT A (VCCO_87_88)
- Mezzanine Connector MC3
- Port A uses Bank 88 which is an HD bank that has a wider VIO range, but does not support LVDS.
- GC
- B88_L5P
- B88_L5N
- B88_L1P
- B88_L9P
- B88_L9N
- B88_L4P
- B88_L1N
- B88_L6P
- B88_L6N
- B88_L2P
- B88_L2N
- B88_L4N
- B88_L8P
- B88_L8N
- B88_L12P
- B88_L12N
- B88_L7P
- B88_L7N
- B88_L3P
- B88_L3N
- B88_L10P
- B88_L10N
- B88_L11P
- B88_L11N
- B87_L2P
- B87_L9P
- B87_L9N
- B87_L10P
- B87_L10N
- B87_L11P
- B87_L2N
- B87_L7P
- B87_L7N
- B87_L5P
- B87_L5N
- B87_L11N
- B87_L12P
- B87_L12N
- B87_L8P
- B87_L8N
- B87_L1P
- B87_L1N
- B87_L4P
- B87_L4N
- B87_L3P
- B87_L6P
- B87_L6N
- B68_L7P_N0
- B68_L7N_N1
- B87_L3N
- B68_L1P_N0
- B68_L1N_N1
- B68_L5P_N8
- B68_L19N_N1
- B68_L19P_N0
- B68_L5N_N9
- B68_T1U_N12
- SYZYGY PORT B (VCCO_68)
- B68_L21P_N4
- B68_L21N_N5
- B68_T3U_N12
- B68_L23P_N8
- B68_L12P_N10
- B68_L12N_N11
- B68_L9P_N4
- B68_L9N_N5
- B68_L23N_N9
- B68_L8P_N2
- B68_L8N_N3
- B68_L20P_N2
- B68_L20N_N3
- B68_L17P_N8
- B68_L17N_N9
- B68_L22P_N6
- B68_L22N_N7
- B68_L10P_N6
- 2mm Header
- B68_L24P_N10
- B68_L24N_N11
- B68_L11P_N8
- B68_L11N_N9
- B68_L18P_N10
- B68_L10N_N7
- B68_L3P_N4
- B68_L3N_N5
- B68_L13P_N0
- B68_L13N_N1
- B68_L18N_N11
- B68_L2P_N2
- B68_L2N_N3
- B68_T0U_N12
- B68_L6P_N10
- B68_L16P_N6
- B68_L16N_N7
- B68_L15P_N4
- B68_L15N_N5
- B68_L6N_N11
- B68_T2U_N12
- B67_L5P_N8
- B67_L5N_N9
- B68_L4P_N6
- B68_L4N_N7
- B67_L6P_N10
- B68_L14P_N2
- B68_L14N_N3
- B67_L4P_N6
- B67_L4N_N7
- B67_L3P_N4
- B67_L3N_N5
- B67_L2P_N2
- B67_L6N_N11
- B67_L22P_N6
- (near TP14) B67_L22N_N7
- (near TP14) B67_T0U_N12
- (near TP14) B67_T1U_N12
- B67_L2N_N3
- B67_L1P_N0
- B67_L1N_N1
- B67_L8P_N2
- B67_L8N_N3
- B67_L20P_N2
- B67_L20N_N3
- B67_L14P_N2
- B67_L14N_N3
- B67_L10P_N6
- B67_L10N_N7
- B67_L15P_N4
- B67_L15N_N5
- B67_L7P_N0
- B67_L24P_N10
- B67_L24N_N11
- B67_L13P_N0
- B67_L13N_N1
- B67_T3U_N12
- SYZYGY PORT C (VCCO_67)
- B67_L7N_N1
- B67_T2U_N12
- B67_L12P_N10
- B67_L12N_N11
- B67_L19P_N0
- B67_L23P_N8
- B67_L23N_N9
- B67_L9P_N4
- B67_L9N_N5
- B67_L16P_N6
- B67_L19N_N1
- B67_L17P_N8
- B67_L17N_N9
- B67_L21P_N4
- B67_L21N_N5
- B67_L16N_N7
- B67_L18P_N10
- B67_L18N_N11
- +VDCIN: +6 to +12 VDC
- Title
- Size:
- Date:
- C
- Number:
- Time:
- Revision:
- Sheet
- of

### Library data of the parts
C20 C21 = 001073: Ceramic capacitor; Manufacturer: Taiyo Yuden; partnumber: 001073; ValueFloat: 1E-7; x_tolerance: 10
C218 C219 = 000070: Partnumber: 000070; manufacturer: Kemet; ValueFloat: 1E-7; x_tolerance: 10
J8 J9 J11 = 001604: 0.8mm hi-speed, high-density header (male); Manufacturer: Samtec; partnumber: 001604; Description 2: 40-pin, ground protection in middle
J10 = 001938: 2mm header, 6x2, thru-hole; Partnumber: 001938; Manufacturer: Molex
MC3 = 000876: 0.5mm Double Row High Speed Socket Assembly; Partnumber: 000876; manufacturer: Samtec
R16 = 001549: Thick-film resistor; Manufacturer: Vishay; partnumber: 001549; ValueFloat: 210000; x_tolerance: 1
R17 = 001550: Thick-film resistor; Manufacturer: Vishay; partnumber: 001550; ValueFloat: 84500; x_tolerance: 1
R18 = 001035: Partnumber: 001035; manufacturer: Vishay; ValueFloat: 49900; x_tolerance: 1
R151 R152 = 000755: Partnumber: 000755; manufacturer: Vishay; x_tolerance: 1
TP14 = TP-PTH-25/45: Test point, plated through-hole, 25/45mil; partnumber: ALIGNI_IGNORE
U34 = 002140: Level Translator, 0.65V - 3.6V, Direction Control; Partnumber: 002140; Manufacturer: Texas Instruments; Description 2: Single Bit, Dual Supplies, SC70-6

## Sheet Power.SchDoc: BRK1900 - Power
size C; Organization: Opal Kelly; Address1: 13500 SW 72nd Ave STE 100; Address2: Portland, OR  97223; Address3: 217.391.3724; Address4: http://www.opalkelly.com; DocumentNumber: 6; Revision: 1; SheetNumber: 6; SheetTotal: 11; PageSetup: Record=PageOptions¦CenterHorizontal=True¦CenterVertical=True¦PrintScale=0.52¦XCorrection=1.00¦YCorrection=1.00¦PrintKind=0¦BorderSize=5000000¦LeftOffset=0¦BottomOffset=0¦Orientation=2¦PaperLength=1000¦PaperWidth=1000¦Scale=100¦PaperSource=7¦PrintQuality=-4¦MediaType=1¦DitherType=10¦PaperKind=Letter¦PrintScaleMode=1
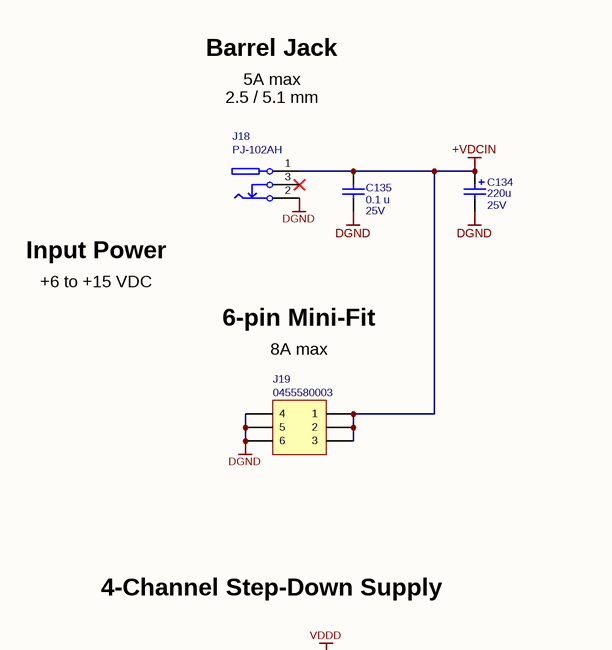
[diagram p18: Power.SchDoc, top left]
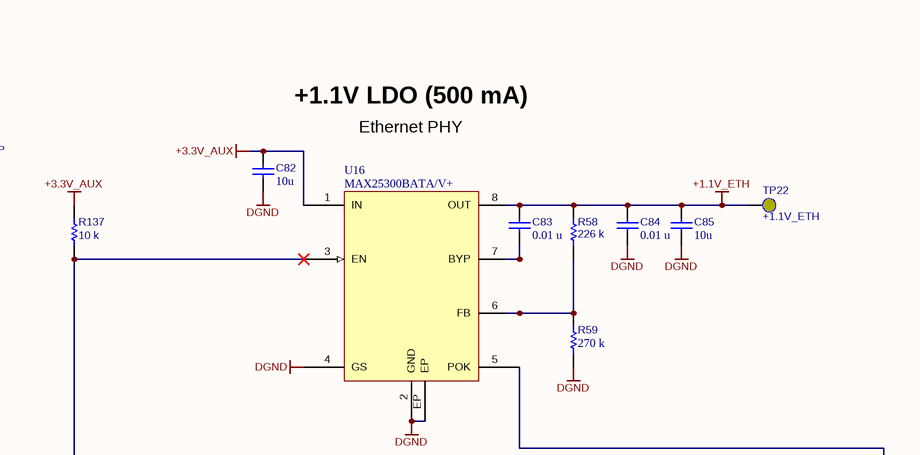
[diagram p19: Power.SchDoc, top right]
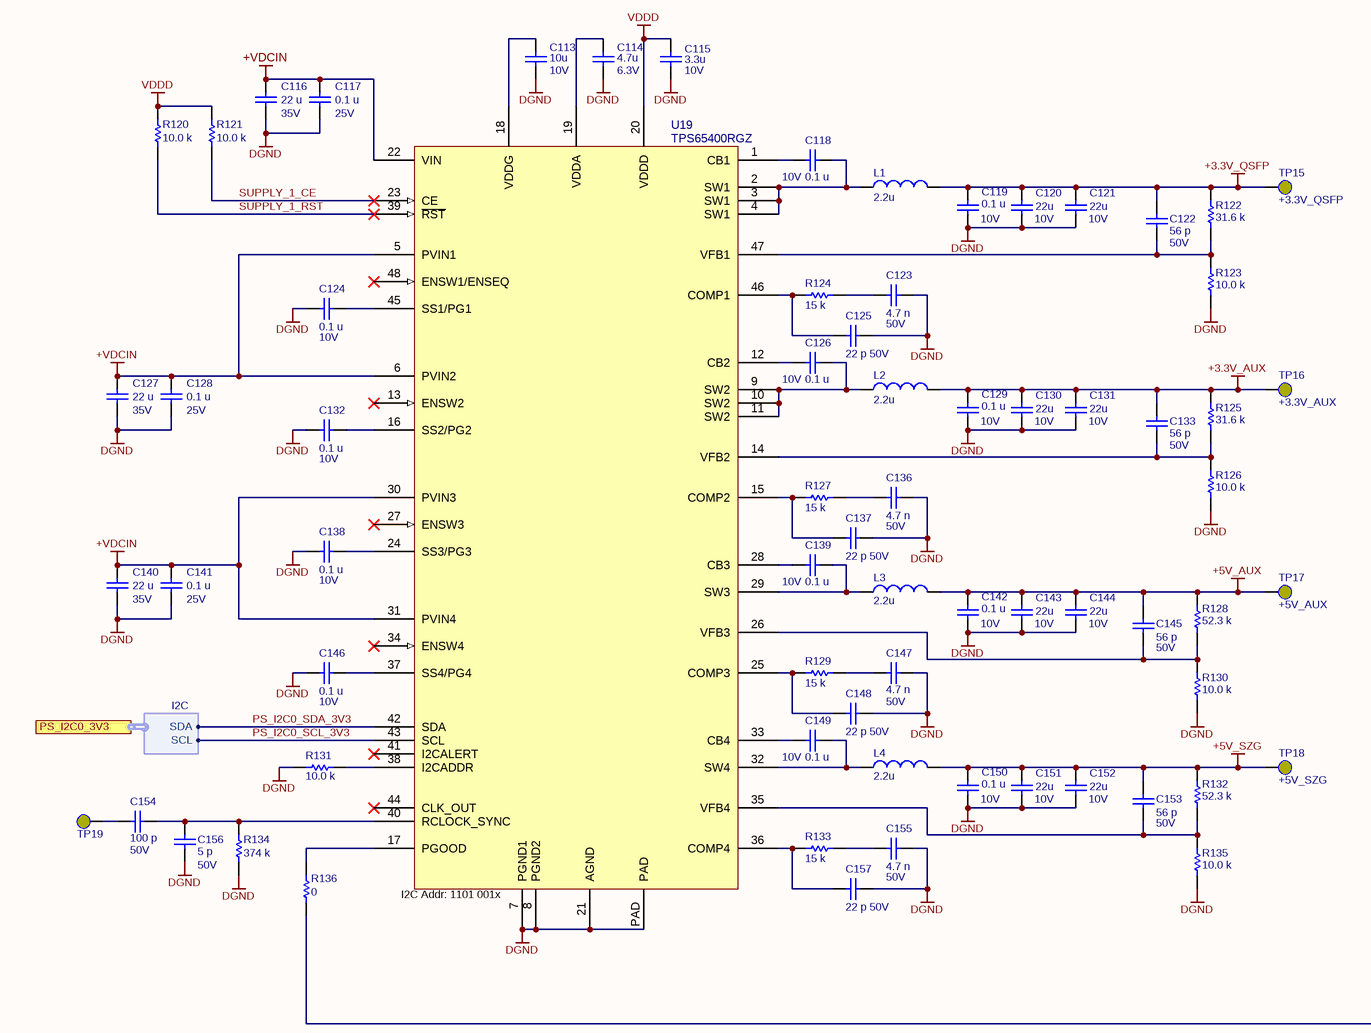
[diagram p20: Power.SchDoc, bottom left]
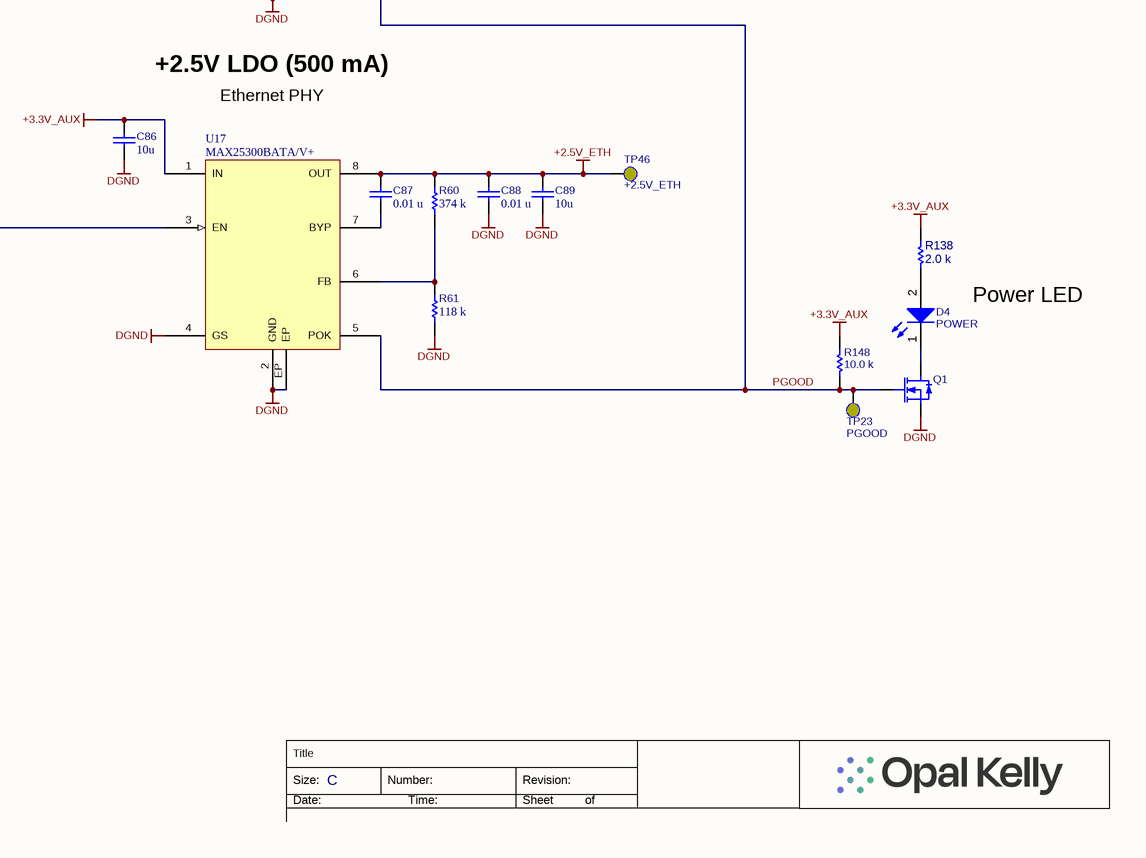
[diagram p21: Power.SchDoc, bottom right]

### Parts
C82  value 10u  [CAPC2012X14N]  (hidden comment: EMK212BJ106KG-T)
C83  value 0.01 u  [CAPC1005X06A]  (hidden comment: C0402C103K4RACTU)
C84  value 0.01 u  [CAPC1005X06A]  (hidden comment: C0402C103K4RACTU)
C85  value 10u  [CAPC2012X14N]  (hidden comment: EMK212BJ106KG-T)
C86  value 10u  [CAPC2012X14N]  (hidden comment: EMK212BJ106KG-T)
C87  value 0.01 u  [CAPC1005X06A]  (hidden comment: C0402C103K4RACTU)
C88  value 0.01 u  [CAPC1005X06A]  (hidden comment: C0402C103K4RACTU)
C89  value 10u  [CAPC2012X14N]  (hidden comment: EMK212BJ106KG-T)
C113  value 10u  Voltage: 10V  [CAPC1608X09N]  (hidden comment: LMK107BJ106MALTD)
C114  value 4.7u  Voltage: 6.3V  [CAPC1005X06A]  (hidden comment: JMK105BBJ475MV-F)
C115  value 3.3u  Voltage: 10V  [CAPC1005X06A]  (hidden comment: C1005X5R1A335K050BC)
C116  value 22 u  Voltage: 35V  [CAPC3216N]  (hidden comment: C3216X5R1V226M160AC)
C117  value 0.1 u  Voltage: 25V  [CAPC1005X06A]  (hidden comment: TMK105BJ104KV-F)
C118  value 0.1 u  Voltage: 10V  [CAPC1005X06A]  (hidden comment: C0402C104K8PACTU)
C119  value 0.1 u  Voltage: 10V  [CAPC1005X06A]  (hidden comment: C0402C104K8PACTU)
C120  value 22u  Voltage: 10V  [CAPC3216N]  (hidden comment: LMK316AB7226KL-TR)
C121  value 22u  Voltage: 10V  [CAPC3216N]  (hidden comment: LMK316AB7226KL-TR)
C122  value 56 p  Voltage: 50V  [CAPC1005X06A]  (hidden comment: SM-0402, 5%, 50v)
C123  value 4.7 n  Voltage: 50V  [CAPC1005X06A]  (hidden comment: C0402C472K5RACTU)
C124  value 0.1 u  Voltage: 10V  [CAPC1005X06A]  (hidden comment: C0402C104K8PACTU)
C125  value 22 p  Voltage: 50V  [CAPC1005X06A]  (hidden comment: C0402C220J5GACTU)
C126  value 0.1 u  Voltage: 10V  [CAPC1005X06A]  (hidden comment: C0402C104K8PACTU)
C127  value 22 u  Voltage: 35V  [CAPC3216N]  (hidden comment: C3216X5R1V226M160AC)
C128  value 0.1 u  Voltage: 25V  [CAPC1005X06A]  (hidden comment: TMK105BJ104KV-F)
C129  value 0.1 u  Voltage: 10V  [CAPC1005X06A]  (hidden comment: C0402C104K8PACTU)
C130  value 22u  Voltage: 10V  [CAPC3216N]  (hidden comment: LMK316AB7226KL-TR)
C131  value 22u  Voltage: 10V  [CAPC3216N]  (hidden comment: LMK316AB7226KL-TR)
C132  value 0.1 u  Voltage: 10V  [CAPC1005X06A]  (hidden comment: C0402C104K8PACTU)
C133  value 56 p  Voltage: 50V  [CAPC1005X06A]  (hidden comment: SM-0402, 5%, 50v)
C134  value 220u  Voltage: 25V  [CAPAE9083X70N]  (hidden comment: EEE-FK1E221P)
C135  value 0.1 u  Voltage: 25V  [CAPC1005X06A]  (hidden comment: TMK105BJ104KV-F)
C136  value 4.7 n  Voltage: 50V  [CAPC1005X06A]  (hidden comment: C0402C472K5RACTU)
C137  value 22 p  Voltage: 50V  [CAPC1005X06A]  (hidden comment: C0402C220J5GACTU)
C138  value 0.1 u  Voltage: 10V  [CAPC1005X06A]  (hidden comment: C0402C104K8PACTU)
C139  value 0.1 u  Voltage: 10V  [CAPC1005X06A]  (hidden comment: C0402C104K8PACTU)
C140  value 22 u  Voltage: 35V  [CAPC3216N]  (hidden comment: C3216X5R1V226M160AC)
C141  value 0.1 u  Voltage: 25V  [CAPC1005X06A]  (hidden comment: TMK105BJ104KV-F)
C142  value 0.1 u  Voltage: 10V  [CAPC1005X06A]  (hidden comment: C0402C104K8PACTU)
C143  value 22u  Voltage: 10V  [CAPC3216N]  (hidden comment: LMK316AB7226KL-TR)
C144  value 22u  Voltage: 10V  [CAPC3216N]  (hidden comment: LMK316AB7226KL-TR)
C145  value 56 p  Voltage: 50V  [CAPC1005X06A]  (hidden comment: C0402C560J5GACTU)
C146  value 0.1 u  Voltage: 10V  [CAPC1005X06A]  (hidden comment: C0402C104K8PACTU)
C147  value 4.7 n  Voltage: 50V  [CAPC1005X06A]  (hidden comment: C0402C472K5RACTU)
C148  value 22 p  Voltage: 50V  [CAPC1005X06A]  (hidden comment: C0402C220J5GACTU)
C149  value 0.1 u  Voltage: 10V  [CAPC1005X06A]  (hidden comment: C0402C104K8PACTU)
C150  value 0.1 u  Voltage: 10V  [CAPC1005X06A]  (hidden comment: C0402C104K8PACTU)
C151  value 22u  Voltage: 10V  [CAPC3216N]  (hidden comment: LMK316AB7226KL-TR)
C152  value 22u  Voltage: 10V  [CAPC3216N]  (hidden comment: LMK316AB7226KL-TR)
C153  value 56 p  Voltage: 50V  [CAPC1005X06A]  (hidden comment: C0402C560J5GACTU)
C154  value 100 p  Voltage: 50V  [CAPC1005X06A]  (hidden comment: SM-0402, 5%, 50V, NP0)
C155  value 4.7 n  Voltage: 50V  [CAPC1005X06A]  (hidden comment: C0402C472K5RACTU)
C156  value 5 p  Voltage: 50V  [CAPC1005X06A]  (hidden comment: GJM1555C1H5R0CB01D)
C157  value 22 p  Voltage: 50V  [CAPC1005X06A]  (hidden comment: C0402C220J5GACTU)
D4  POWER  [CD1608-0603-PIN1-CATHODE]
J18  PJ-102AH  [CUI-PJ102A]
J19  0455580003  [0455580003]
L1  value 2.2u  [XAL60XX]  (hidden comment: XAL6030-222MEB)
L2  value 2.2u  [XAL60XX]  (hidden comment: XAL6030-222MEB)
L3  value 2.2u  [VLS4012CX]  (hidden comment: VLS4012CX-2R2M-1)
L4  value 2.2u  [VLS4012CX]  (hidden comment: VLS4012CX-2R2M-1)
Q1  2.2A, 30V  [SOT23-95P240X110]  (value not drawn)
R58  value 226 k  [RESC1005X06A]  (hidden comment: CRCW0402226KFKED)
R59  value 270 k  [RESC1005X06A]  (hidden comment: CRCW0402270KFKED)
R60  value 374 k  [RESC1005X06A]  (hidden comment: CRCW0402374KFKED)
R61  value 118 k  [RESC1005X06A]  (hidden comment: CRCW0402118KFKED)
R120  value 10.0 k  [RESC1005X06A]  (hidden comment: CRCW040210K0FKED)
R121  value 10.0 k  [RESC1005X06A]  (hidden comment: CRCW040210K0FKED)
R122  value 31.6 k  [RESC1005X06A]  (hidden comment: SM-0402, 1%, 1/16W)
R123  value 10.0 k  [RESC1005X06A]  (hidden comment: SM-0402, 1%, 1/16W)
R124  value 15 k  [RESC1005X06A]  (hidden comment: CRCW040215K0FKED)
R125  value 31.6 k  [RESC1005X06A]  (hidden comment: SM-0402, 1%, 1/16W)
R126  value 10.0 k  [RESC1005X06A]  (hidden comment: SM-0402, 1%, 1/16W)
R127  value 15 k  [RESC1005X06A]  (hidden comment: CRCW040215K0FKED)
R128  value 52.3 k  [RESC1005X06A]  (hidden comment: CRCW040252K3FKED)
R129  value 15 k  [RESC1005X06A]  (hidden comment: CRCW040215K0FKED)
R130  value 10.0 k  [RESC1005X06A]  (hidden comment: SM-0402, 1%, 1/16W)
R131  value 10.0 k  [RESC1005X06A]  (hidden comment: CRCW040210K0FKED)
R132  value 52.3 k  [RESC1005X06A]  (hidden comment: CRCW040252K3FKED)
R133  value 15 k  [RESC1005X06A]  (hidden comment: CRCW040215K0FKED)
R134  value 374 k  [RESC1005X06A]  (hidden comment: CRCW0402374KFKED)
R135  value 10.0 k  [RESC1005X06A]  (hidden comment: SM-0402, 1%, 1/16W)
R136  value 0  [RESC1608N]  (hidden comment: CRCW06030000Z0EA)
R137  value 10 k  [RESC1005X06A]  (hidden comment: CRCW040210K0JNED)
R138  value 2.0 k  [RESC1005X06A]  (hidden comment: CRCW04022K00FKED)
R148  value 10.0 k  [RESC1005X06A]  (hidden comment: CRCW040210K0FKED)
TP15  +3.3V_QSFP  [TP-SMD40]
TP16  +3.3V_AUX  [TP-SMD40]
TP17  +5V_AUX  [TP-SMD40]
TP18  +5V_SZG  [TP-SMD40]
TP19  TESTPOINT-SMD40  [TP-SMD40]  (value not drawn)
TP22  +1.1V_ETH  [TP-SMD40]
TP23  PGOOD  [TP-SMD40]
TP46  +2.5V_ETH  [TP-SMD40]
U16  MAX25300BATA/V+  [MAX25300]
U17  MAX25300BATA/V+  [MAX25300]
U19  TPS65400RGZ  [PVQFN-48]

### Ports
PS_I2C0_3V3 (harness I2C)

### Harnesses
I2C: SCL, SDA

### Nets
+1.1V_ETH: C83.2 C84.2 C85.2 R58.2 TP22.1(PIN) U16.8(OUT)
+2.5V_ETH: C87.2 C88.2 C89.2 R60.2 TP46.1(PIN) U17.8(OUT)
+3.3V_AUX: C82.2 C86.2 C129.2 C130.2 C131.2 C133.2 L2.2 R125.2 R137.2 R138.2 R148.2 TP16.1(PIN) U16.1(IN) U17.1(IN)
+3.3V_QSFP: C119.2 C120.2 C121.2 C122.2 L1.2 R122.2 TP15.1(PIN)
+5V_AUX: C142.2 C143.2 C144.2 C145.2 L3.2 R128.2 TP17.1(PIN)
+5V_SZG: C150.2 C151.2 C152.2 C153.2 L4.2 R132.2 TP18.1(PIN)
+VDCIN: C116.1 C117.1 C127.1 C128.1 C134.1 C135.2 C140.1 C141.1 J18.1 J19.1 J19.2 J19.3 U19.5(PVIN1) U19.6(PVIN2) U19.22(VIN) U19.30(PVIN3) U19.31(PVIN4)
DGND: C82.1 C84.1 C85.1 C86.1 C88.1 C89.1 C113.1 C114.1 C115.1 C116.2 C117.2 C119.1 C120.1 C121.1 C123.2 C124.2 C125.2 C127.2 C128.2 C129.1 C130.1 C131.1 C132.1 C134.2 C135.1 C136.2 C137.2 C138.2 C140.2 C141.2 C142.1 C143.1 C144.1 C146.2 C147.2 C148.2 C150.1 C151.1 C152.1 C155.2 C156.1 C157.2 J18.2 J19.4 J19.5 J19.6 Q1.2(S) R59.1 R61.1 R123.1 R126.1 R130.1 R131.2 R134.1 R135.1 U16.2(GND) U16.4(GS) U16.EP U17.2(GND) U17.4(GS) U17.EP U19.7(PGND1) U19.8(PGND2) U19.21(AGND) U19.PAD
VDDD: C115.2 R120.2 R121.2 U19.20(VDDD)
PGOOD: Q1.1(G) R148.1 TP23.1(PIN) U16.5(POK) U17.5(POK)
PS_I2C0_SCL_3V3: U19.43(SCL) ; port PS_I2C0_3V3.SCL
PS_I2C0_SDA_3V3: U19.42(SDA) ; port PS_I2C0_3V3.SDA
SUPPLY_1_CE: R121.1 U19.23(CE)
SUPPLY_1_RST: R120.1 U19.39(~{RST})
NetC83_1: C83.1 U16.7(BYP)
NetC87_1: C87.1 U17.7(BYP)
NetC113_2: C113.2 U19.18(VDDG)
NetC114_2: C114.2 U19.19(VDDA)
NetC118_1: C118.1 U19.1(CB1)
NetC118_2: C118.2 L1.1 U19.2(SW1) U19.3(SW1) U19.4(SW1)
NetC122_1: C122.1 R122.1 R123.2 U19.47(VFB1)
NetC123_1: C123.1 R124.2
NetC124_1: C124.1 U19.45(SS1/PG1)
NetC125_1: C125.1 R124.1 U19.46(COMP1)
NetC126_1: C126.1 U19.12(CB2)
NetC126_2: C126.2 L2.1 U19.9(SW2) U19.10(SW2) U19.11(SW2)
NetC132_2: C132.2 U19.16(SS2/PG2)
NetC133_1: C133.1 R125.1 R126.2 U19.14(VFB2)
NetC136_1: C136.1 R127.2
NetC137_1: C137.1 R127.1 U19.15(COMP2)
NetC138_1: C138.1 U19.24(SS3/PG3)
NetC139_1: C139.1 U19.28(CB3)
NetC139_2: C139.2 L3.1 U19.29(SW3)
NetC145_1: C145.1 R128.1 R130.2 U19.26(VFB3)
NetC146_1: C146.1 U19.37(SS4/PG4)
NetC147_1: C147.1 R129.2
NetC148_1: C148.1 R129.1 U19.25(COMP3)
NetC149_1: C149.1 U19.33(CB4)
NetC149_2: C149.2 L4.1 U19.32(SW4)
NetC153_1: C153.1 R132.1 R135.2 U19.35(VFB4)
NetC154_1: C154.1 TP19.1(PIN)
NetC154_2: C154.2 C156.2 R134.2 U19.40(RCLOCK_SYNC)
NetC155_1: C155.1 R133.2
NetC157_1: C157.1 R133.1 U19.36(COMP4)
NetD4_1: D4.1(K) Q1.3(D)
NetD4_2: D4.2(A) R138.1
NetR58_1: R58.1 R59.2 U16.6(FB)
NetR60_1: R60.1 R61.2 U17.6(FB)
NetR131_1: R131.1 U19.38(I2CADDR)
NetR136_1: R136.1 R137.1 U16.3(EN) U17.3(EN)
NetR136_2: R136.2 U19.17(PGOOD)

Not connected (* = marked no-connect by the designer): J18 3*; U19 13(ENSW2)* 27(ENSW3)* 34(ENSW4)* 41(I2CALERT)* 44(CLK_OUT)* 48(ENSW1/ENSEQ)*

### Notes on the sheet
- Barrel Jack
- 5A max
- 2.5 / 5.1 mm
- +6 to +15 VDC
- Input Power
- 6-pin Mini-Fit
- 8A max
- 4-Channel Step-Down Supply
- +1.1V LDO (500 mA)
- Ethernet PHY
- +2.5V LDO (500 mA)
- Power LED
- (near U19) I2C Addr: 1101 001x
- Title
- Size:
- Date:
- C
- Number:
- Time:
- Revision:
- Sheet
- of

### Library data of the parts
C82 C85 C86 C89 = 001786: Ceramic capacitor; Partnumber: 001786; Manufacturer: Taiyo Yuden; ValueFloat: 1E-5; Tolerance (%): 10; Description 2: SM-0805, 10%, 16V
C83 C84 C87 C88 = 000295: Ceramic Capacitor; Partnumber: 000295; Manufacturer: Kemet; ValueFloat: 1E-8; Tolerance (%): 10; Description 2: SM-0402, 10%, 16V, X5R
C113 = 001346: Partnumber: 001346; manufacturer: Taiyo Yuden; ValueFloat: 1E-5; x_tolerance: 20
C114 = 000824: Partnumber: 000824; manufacturer: Taiyo Yuden; ValueFloat: 4.7E-6; x_tolerance: 20
C115 = 001926: Partnumber: 001926; manufacturer: TDK; ValueFloat: 3.3E-6; x_tolerance: 20
C116 C127 C140 = 001172: Ceramic Capacitor; Manufacturer: TDK; partnumber: 001172; Description 2: SM-1206, 35V, 20%; ValueFloat: 2.2E-5; Tolerance (%): 20; x_voltage-rating: 35
C117 C128 C141 = 001073: Ceramic capacitor; Manufacturer: Taiyo Yuden; partnumber: 001073; Description 2: 0402, 25V; ValueFloat: 1E-7; Tolerance (%): 10
C118 C119 C126 C129 C139 C142 C149 C150 = 000070: as C218 on sheet Expansion-MC3
C120 C121 C130 C131 C143 C144 C151 C152 = 001284: Ceramic capacitor; Manufacturer: Taiyo Yuden; partnumber: 001284; Description 2: SM-1206, 10%, 10v, X7R; ValueFloat: 2.2E-5; Tolerance (%): 10; x_lifecycle_status: Production
C122 C133 = 001004: Partnumber: 001004; manufacturer: Kemet; manufacturer_pn: C0402C560J5GACTU; ValueFloat: 5.6E-11; id: 25707; inventory_price: 0.0024; x_temperature_characteristic: C0G; x_tolerance: 5
C123 C136 C155 = 000930: Ceramic capacitor; Manufacturer: Kemet; partnumber: 000930; Description 2: 0402, 50V; ValueFloat: 4.7E-9; Tolerance (%): 10
C124 C132 C138 C146 = 000070: Ceramic capacitor; Manufacturer: Kemet; partnumber: 000070; Description 2: SM-0402, 10%, 10v; ValueFloat: 1E-7; Tolerance (%): 10
C125 C137 C148 C157 = 000807: Ceramic capacitor; Manufacturer: Kemet; partnumber: 000807; Description 2: SM-0402, 5%, 50v, C0G; ValueFloat: 2.2E-11; Tolerance (%): 5
C134 = 001532: Polarized; Partnumber: 001532; manufacturer: Panasonic; ValueFloat: 0.00022; x_tolerance: 20; x_voltage-rating: 25
C135 = 001073: Partnumber: 001073; manufacturer: Taiyo Yuden; ValueFloat: 1E-7; x_tolerance: 10
C145 C153 = 001004: Ceramic capacitor; Manufacturer: Kemet; partnumber: 001004; Description 2: SM-0402, 5%, 50v; ValueFloat: 5.6E-11; Tolerance (%): 5
C147 = 000930: Partnumber: 000930; manufacturer: Kemet; ValueFloat: 4.7E-9; x_tolerance: 10
C154 = 000400: Partnumber: 000400; manufacturer: Kemet; manufacturer_pn: C0402C101J5GACTU; ValueFloat: 1E-10; id: 3829; inventory_price: 0.003; reorder_quantity: 200
C156 = 000962: Ceramic capacitor; Manufacturer: Murata; partnumber: 000962; Description 2: SM-0402, 50V; ValueFloat: 5E-12; Tolerance (%): 3.125
D4 = 001433: LED; Manufacturer: Dialight; Manufacturer_PN: 598-8070-107F; partnumber: 001433; Description 2: SM-0603, green; x_lifecycle_status: Production
J18 = 000356: Partnumber: 000356; manufacturer: CUI Inc.
J19 = 001950: Partnumber: 001950; manufacturer: Molex
L1 L2 = 001543: Power inductor, 2.2uH, 7A, 12.7mOhm; Manufacturer: Coilcraft; partnumber: 001543; ValueFloat: 2.2E-6; Tolerance (%): 20; x_lifecycle_status: Production
L3 L4 = 002384: Partnumber: 002384; manufacturer: TDK; ValueFloat: 2.2E-6; x_tolerance: 20
Q1 = 001237: N-Channel MOSFET; PartNumber: 001237; manufacturer: Fairchild Semiconductor; manufacturer_pn: FDN337N; PackageDocument: 1995/1996; id: 48493; inventory_price: 0.2466
R58 = 000932: Thick-film resistor; Partnumber: 000932; Manufacturer: Vishay; ValueFloat: 226000; Tolerance (%): 1; Description 2: SM-0402, 1%, 1/16W
R59 = 001281: Thick-film resistor; Partnumber: 001281; Manufacturer: Vishay; ValueFloat: 270000; Tolerance (%): 1; Description 2: SM-0402, 1%, 1/10W
R60 = 001618: Thick-film resistor; Partnumber: 001618; Manufacturer: Vishay; ValueFloat: 374000; Tolerance (%): 1; Description 2: SM-0402, 1%, 1/16W
R61 = 000967: Thick-film resistor; Partnumber: 000967; Manufacturer: Vishay; ValueFloat: 118000; Tolerance (%): 1; Description 2: SM-0402, 1%, 1/16W
R120 R121 R148 = 001521: Thick-film resistor; Manufacturer: Vishay; partnumber: 001521; Description 2: SM-0402, 1%, 1/16W; ValueFloat: 10000; Tolerance (%): 1; x_lifecycle_status: Production
R122 R125 = 001091: Partnumber: 001091; manufacturer: Vishay; manufacturer_pn: CRCW040231K6FKED; ValueFloat: 31600; id: 32220; inventory_price: 0.0015; x_tolerance: 1
R123 R126 R130 R135 = 001521: Partnumber: 001521; manufacturer: Vishay; manufacturer_pn: CRCW040210K0FKED; ValueFloat: 10000; id: 154248; inventory_price: 0.0016; x_tolerance: 1
R124 R127 R129 R133 = 001121: Thick-film resistor; Manufacturer: Vishay; partnumber: 001121; Description 2: SM-0402, 1%, 1/16W; ValueFloat: 15000; Tolerance (%): 1
R128 R132 = 001157: Partnumber: 001157; manufacturer: Vishay; ValueFloat: 52300; x_tolerance: 1
R131 = 001521: Partnumber: 001521; manufacturer: Vishay; ValueFloat: 10000; x_tolerance: 1
R134 = 001618: Thick-film resistor; Manufacturer: Vishay; partnumber: 001618; Description 2: SM-0402, 1%, 1/16W; ValueFloat: 374000; Tolerance (%): 1; x_lifecycle_status: Production
R136 = 000411: Partnumber: 000411; manufacturer: Vishay
R137 = 000759: Partnumber: 000759; manufacturer: Vishay; ValueFloat: 10000; x_tolerance: 5
R138 = 001162: Thick-film resistor; Manufacturer: Vishay; partnumber: 001162; Description 2: SM-0402, 1%, 1/16W; ValueFloat: 2000; Tolerance (%): 1
TP15-TP19 TP22 TP23 TP46 = TESTPOINT-SMD40: Test point, surface-mount, 40mil
U16 U17 = 002102: LDO, 500 mA, 1.7-5.5V input, 0.6-5.3V output, 1% accuracy; Partnumber: 002102; Manufacturer: Maxim
U19 = 001511: Partnumber: 001511; manufacturer: Texas Instruments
